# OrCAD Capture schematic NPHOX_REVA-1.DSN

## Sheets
1 001 Power: size B; title: npHOx - Power; rev: A
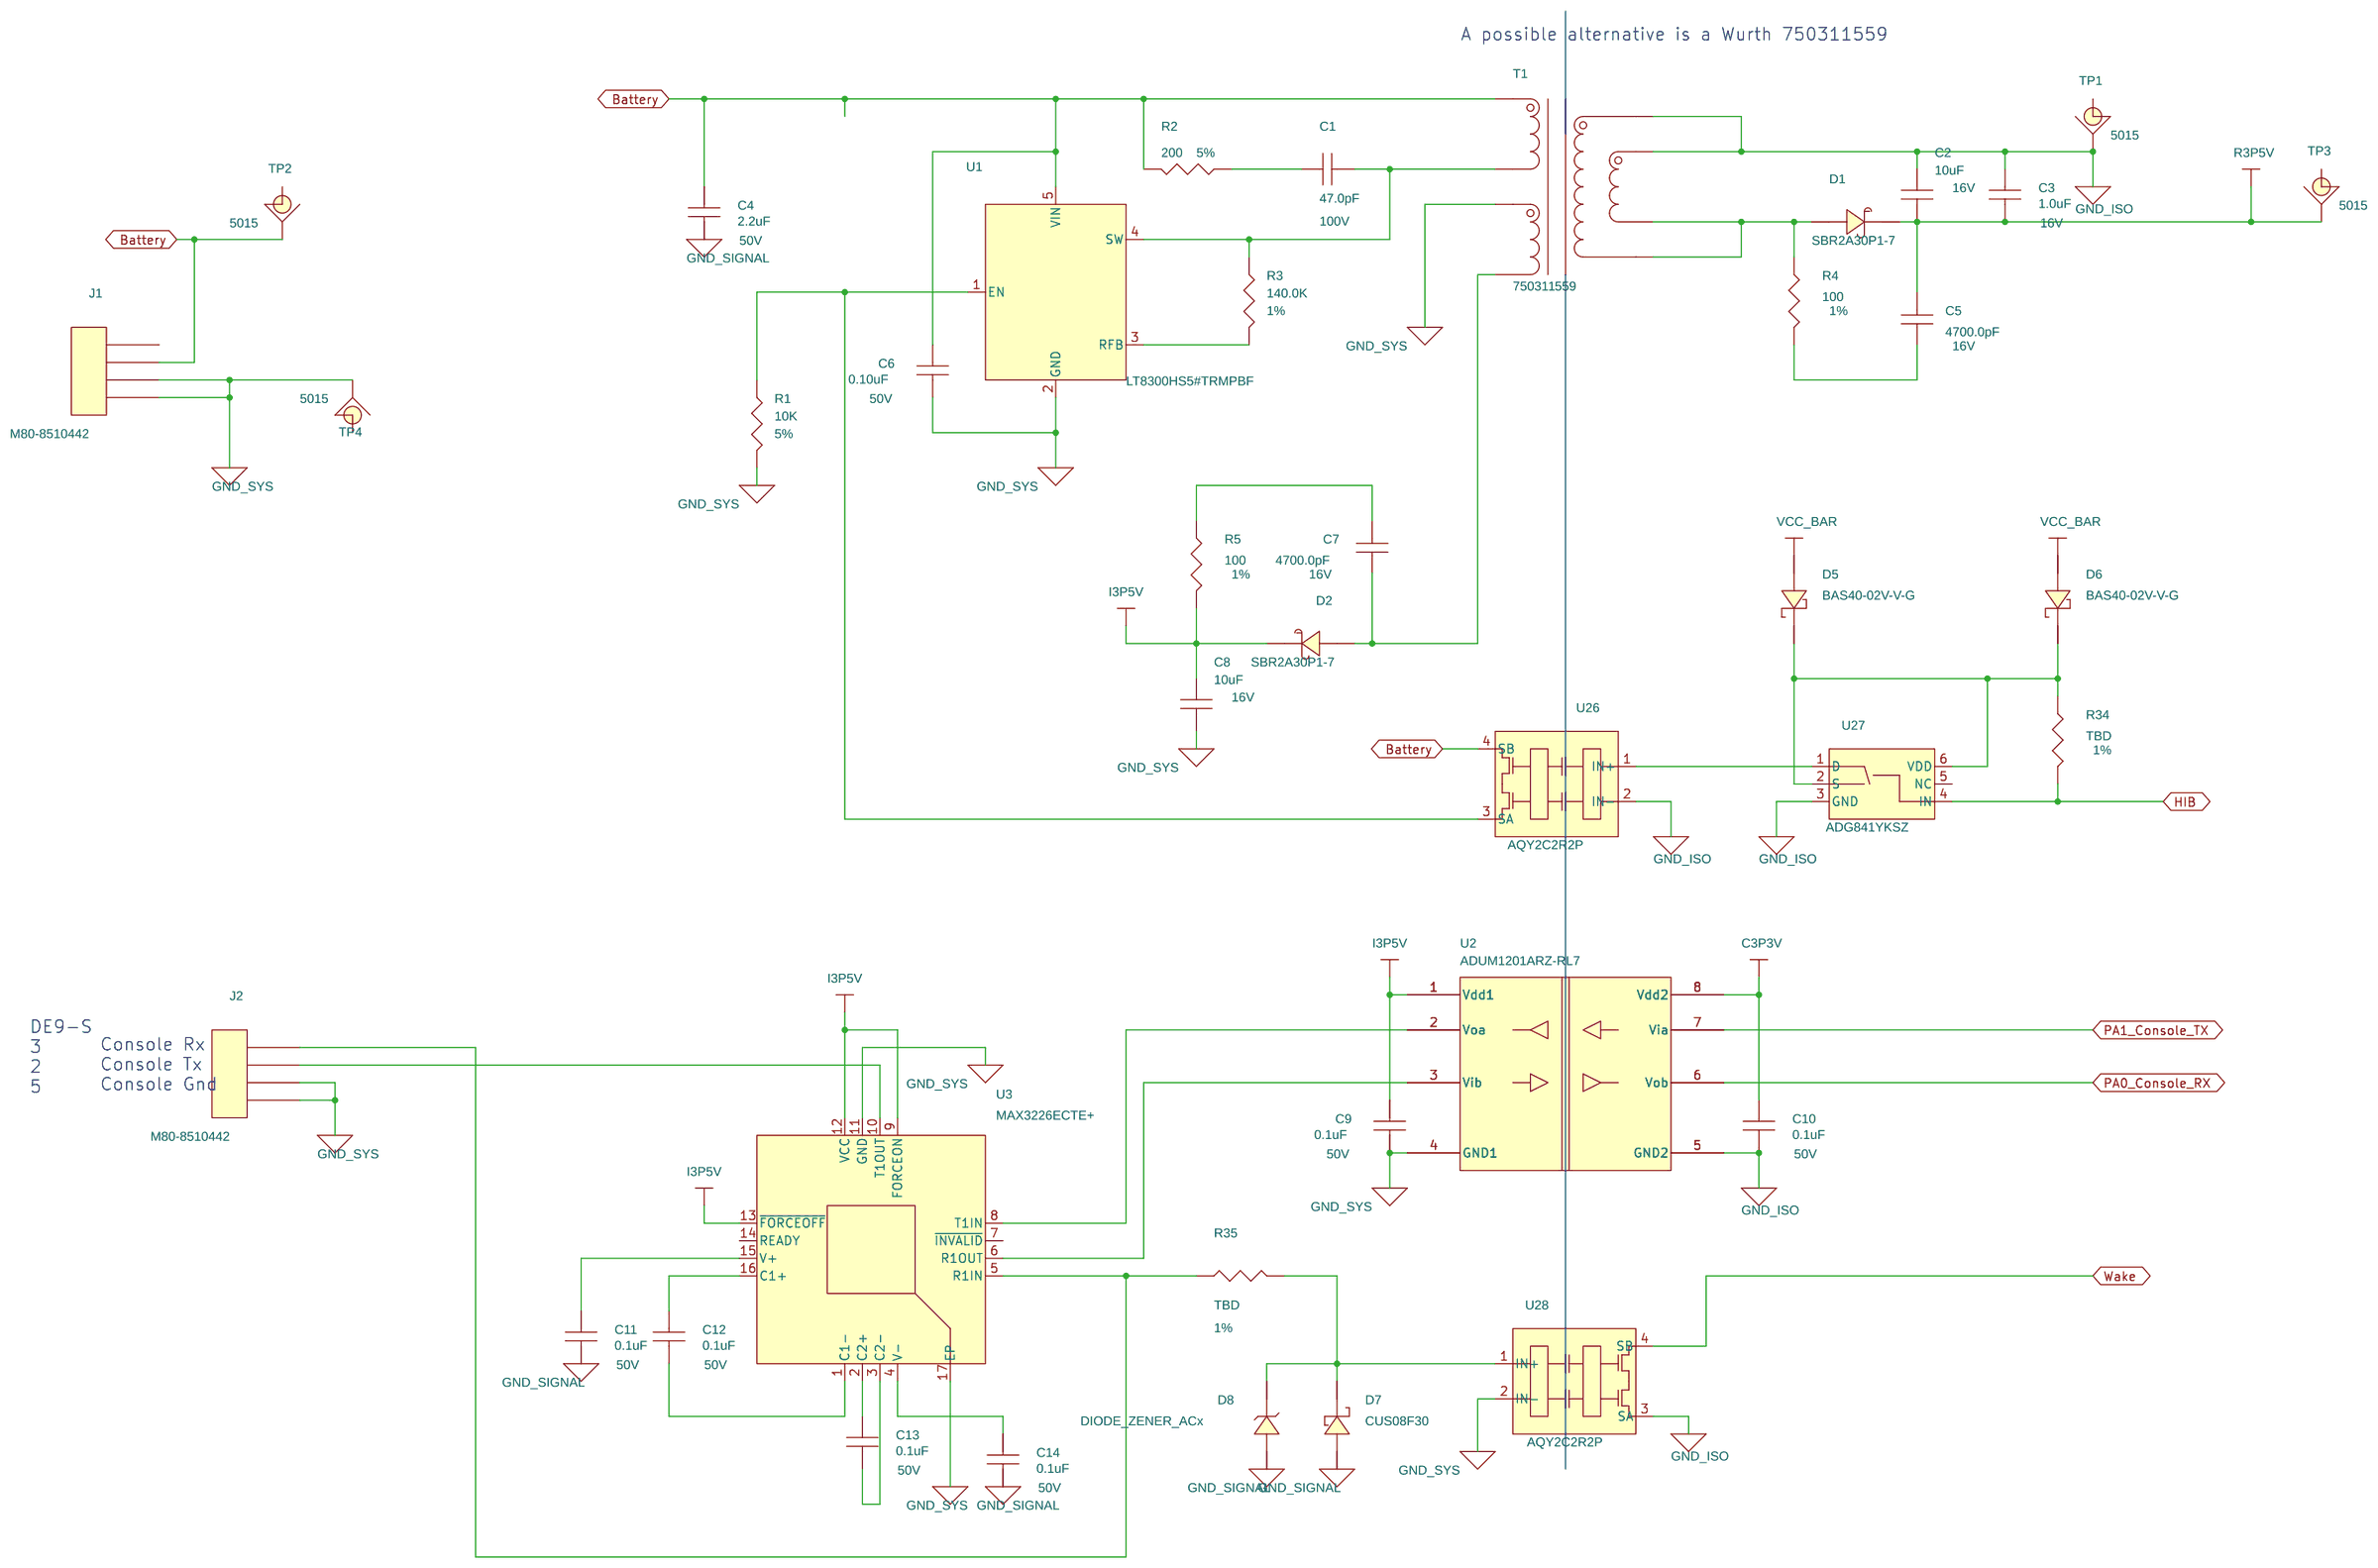
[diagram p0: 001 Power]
2 002 Voltage Regulators: size B; title: npHOx - Voltage Regulators; rev: C; note: 100221250rA
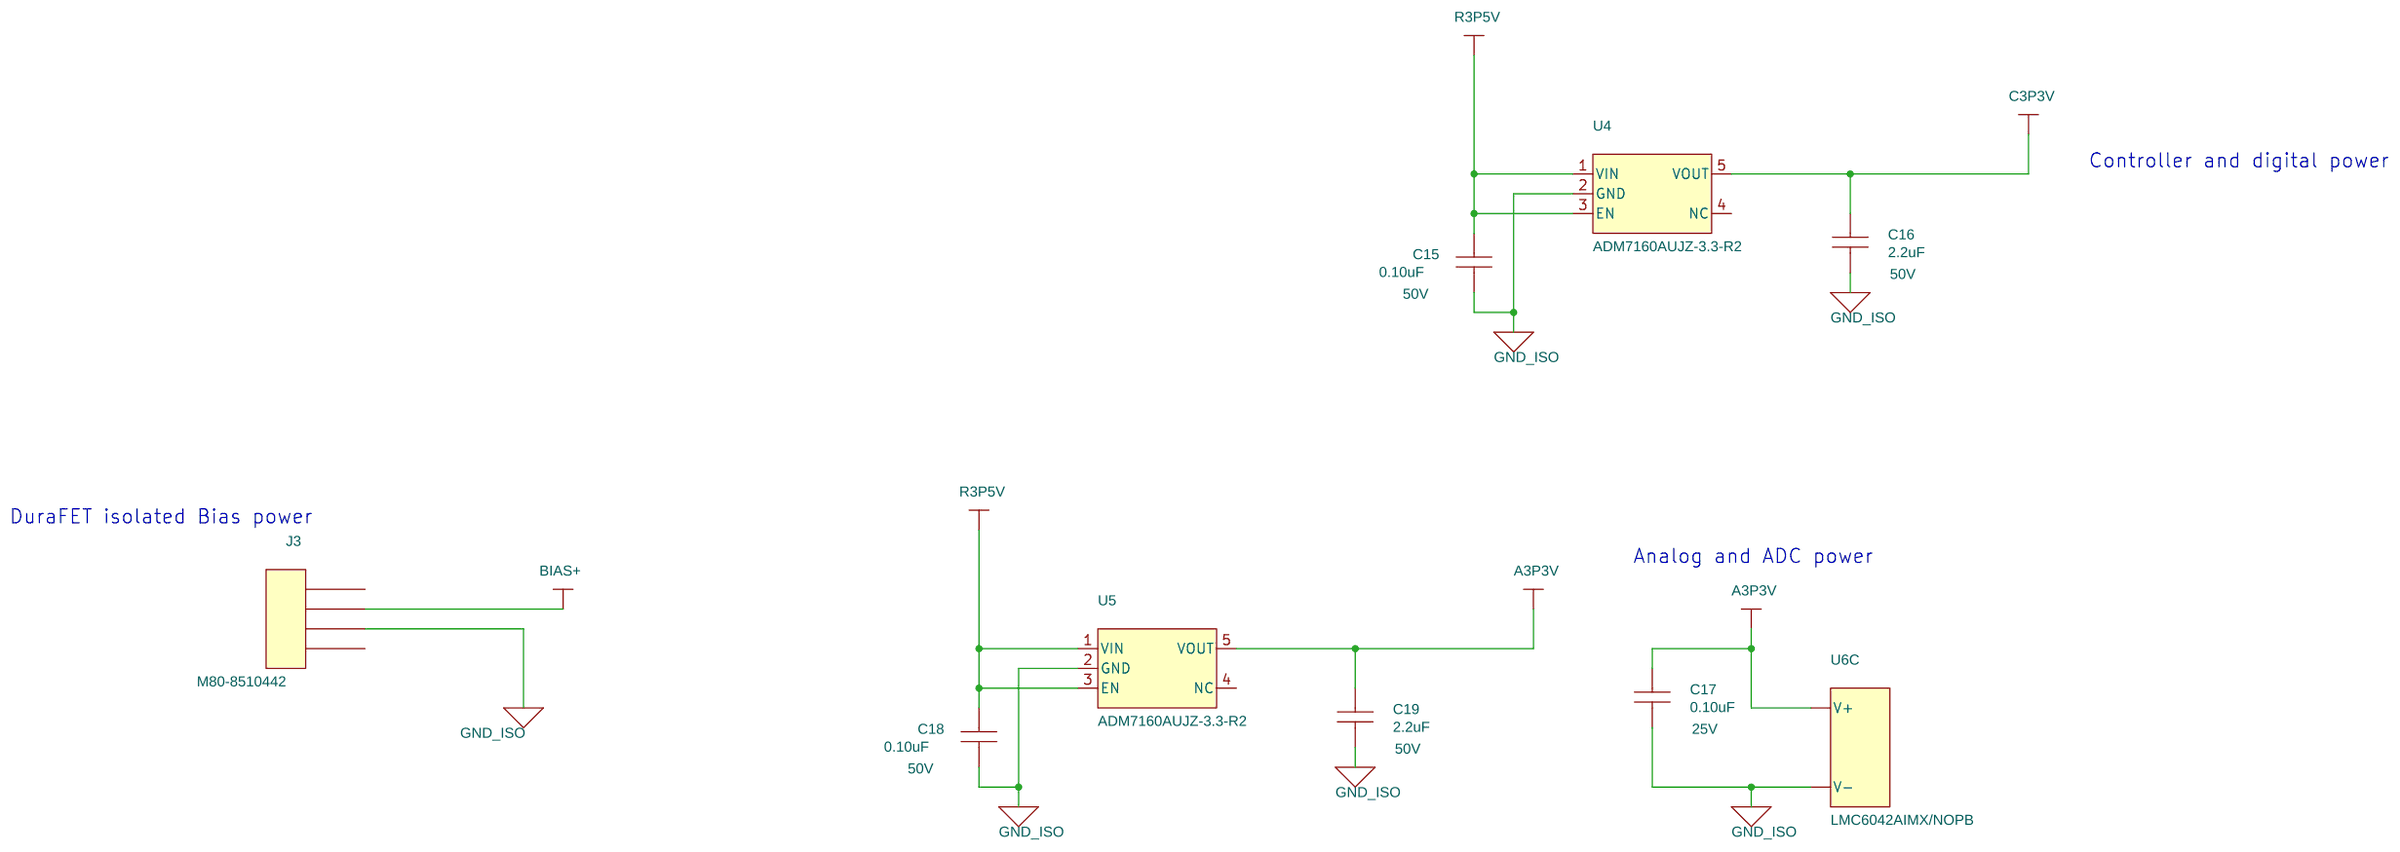
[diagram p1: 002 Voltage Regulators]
3 003 Processor: size B; title: npHOx - Processor
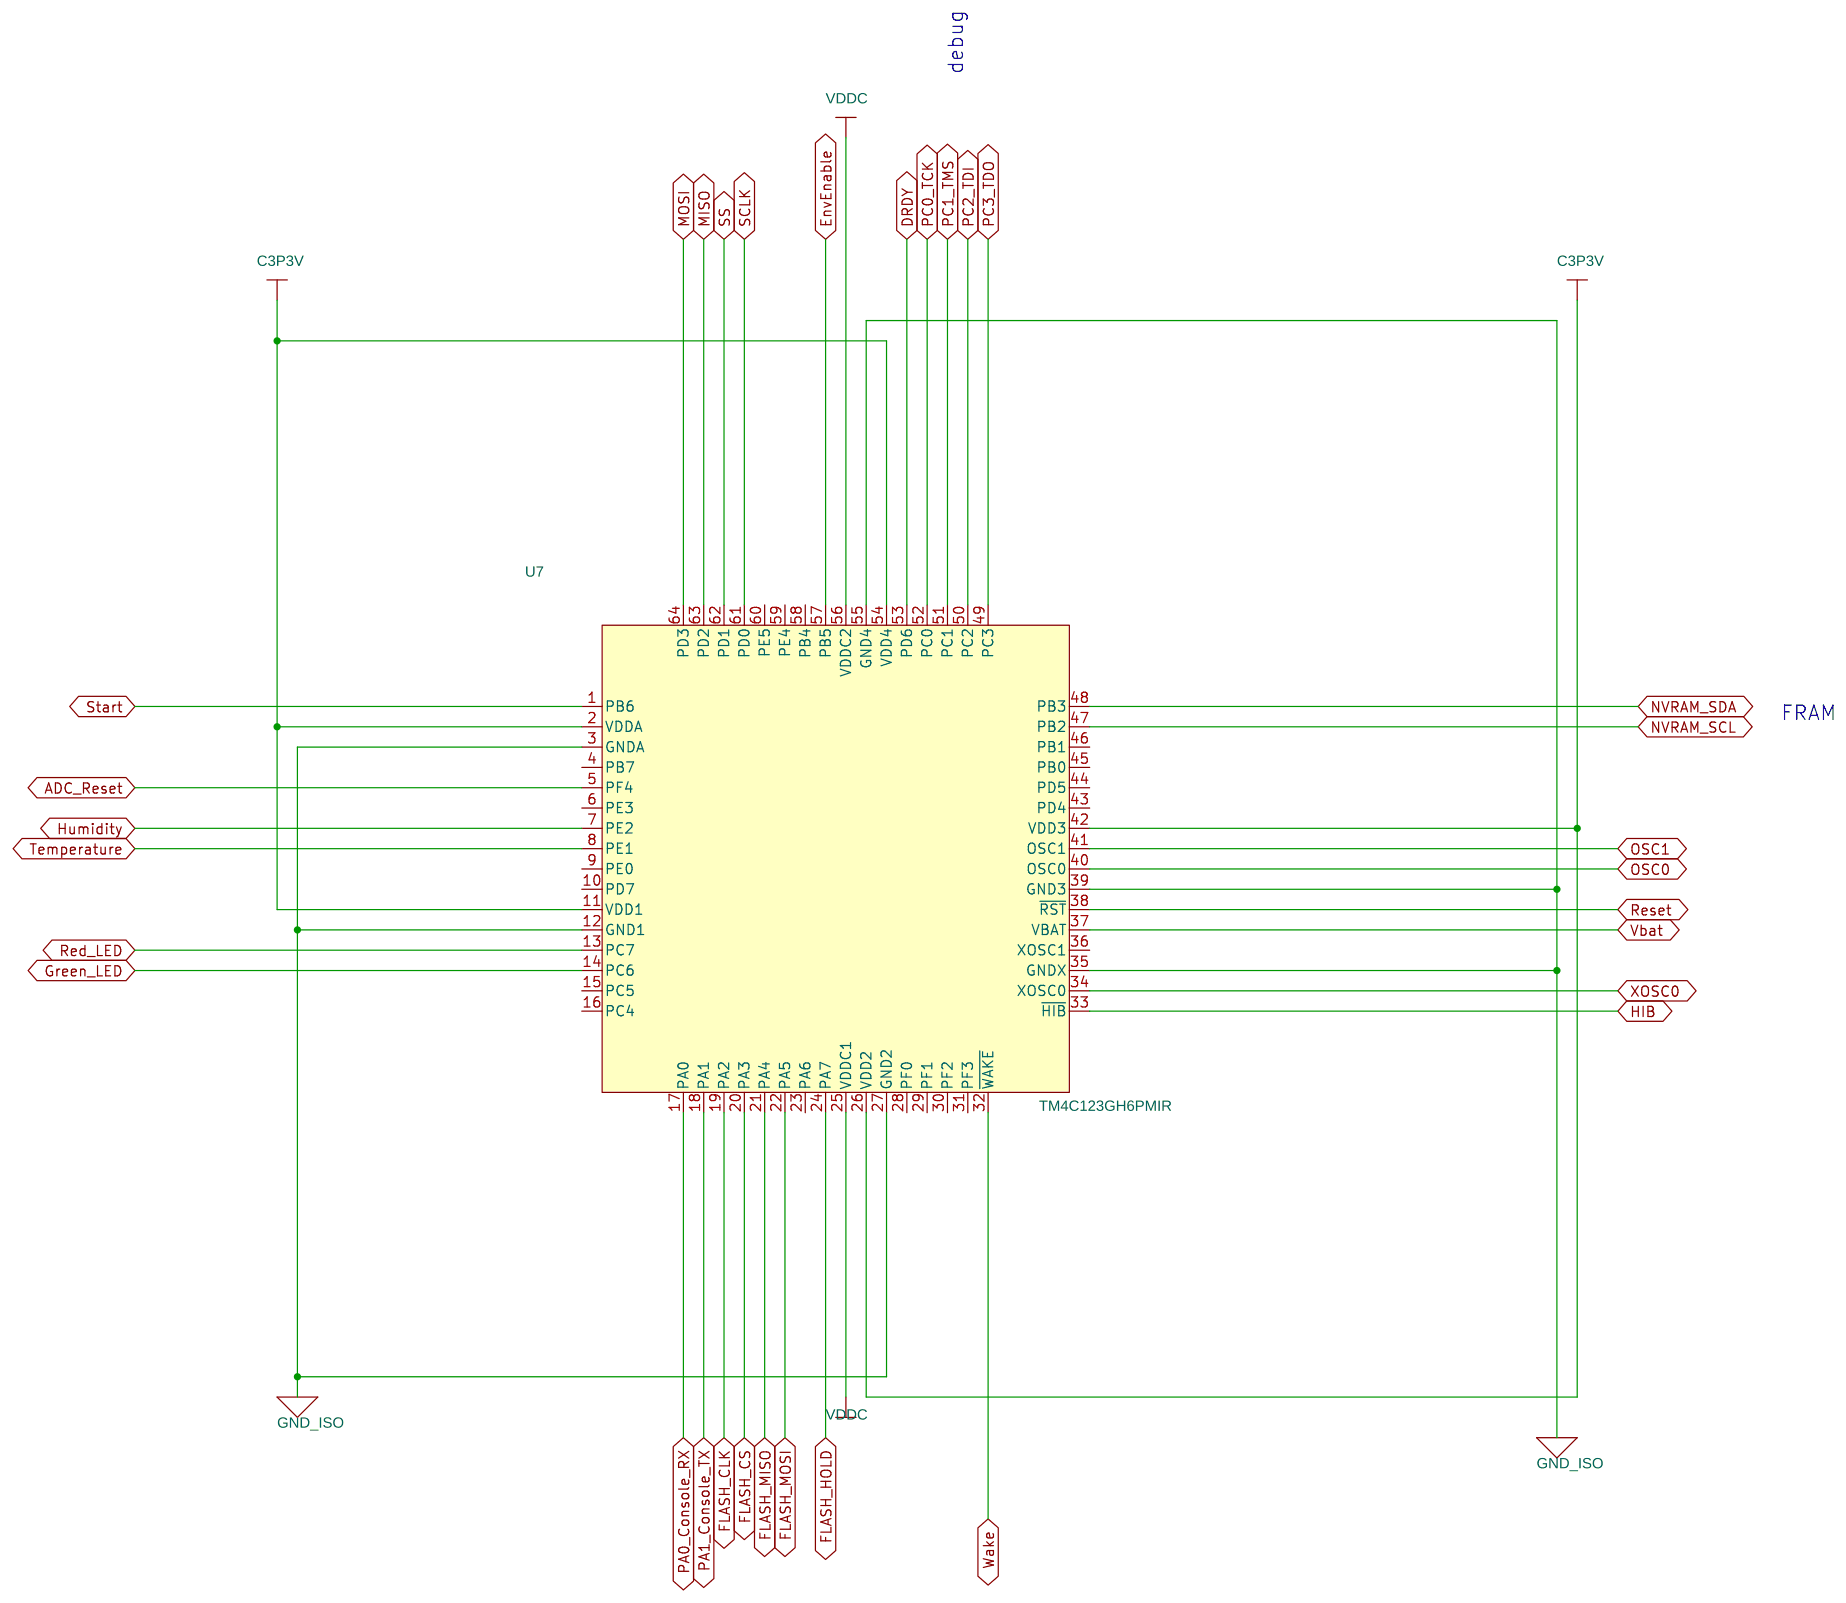
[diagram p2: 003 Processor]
4 004 Processor Bypass: size B; title: npHOx - Processor Bypass
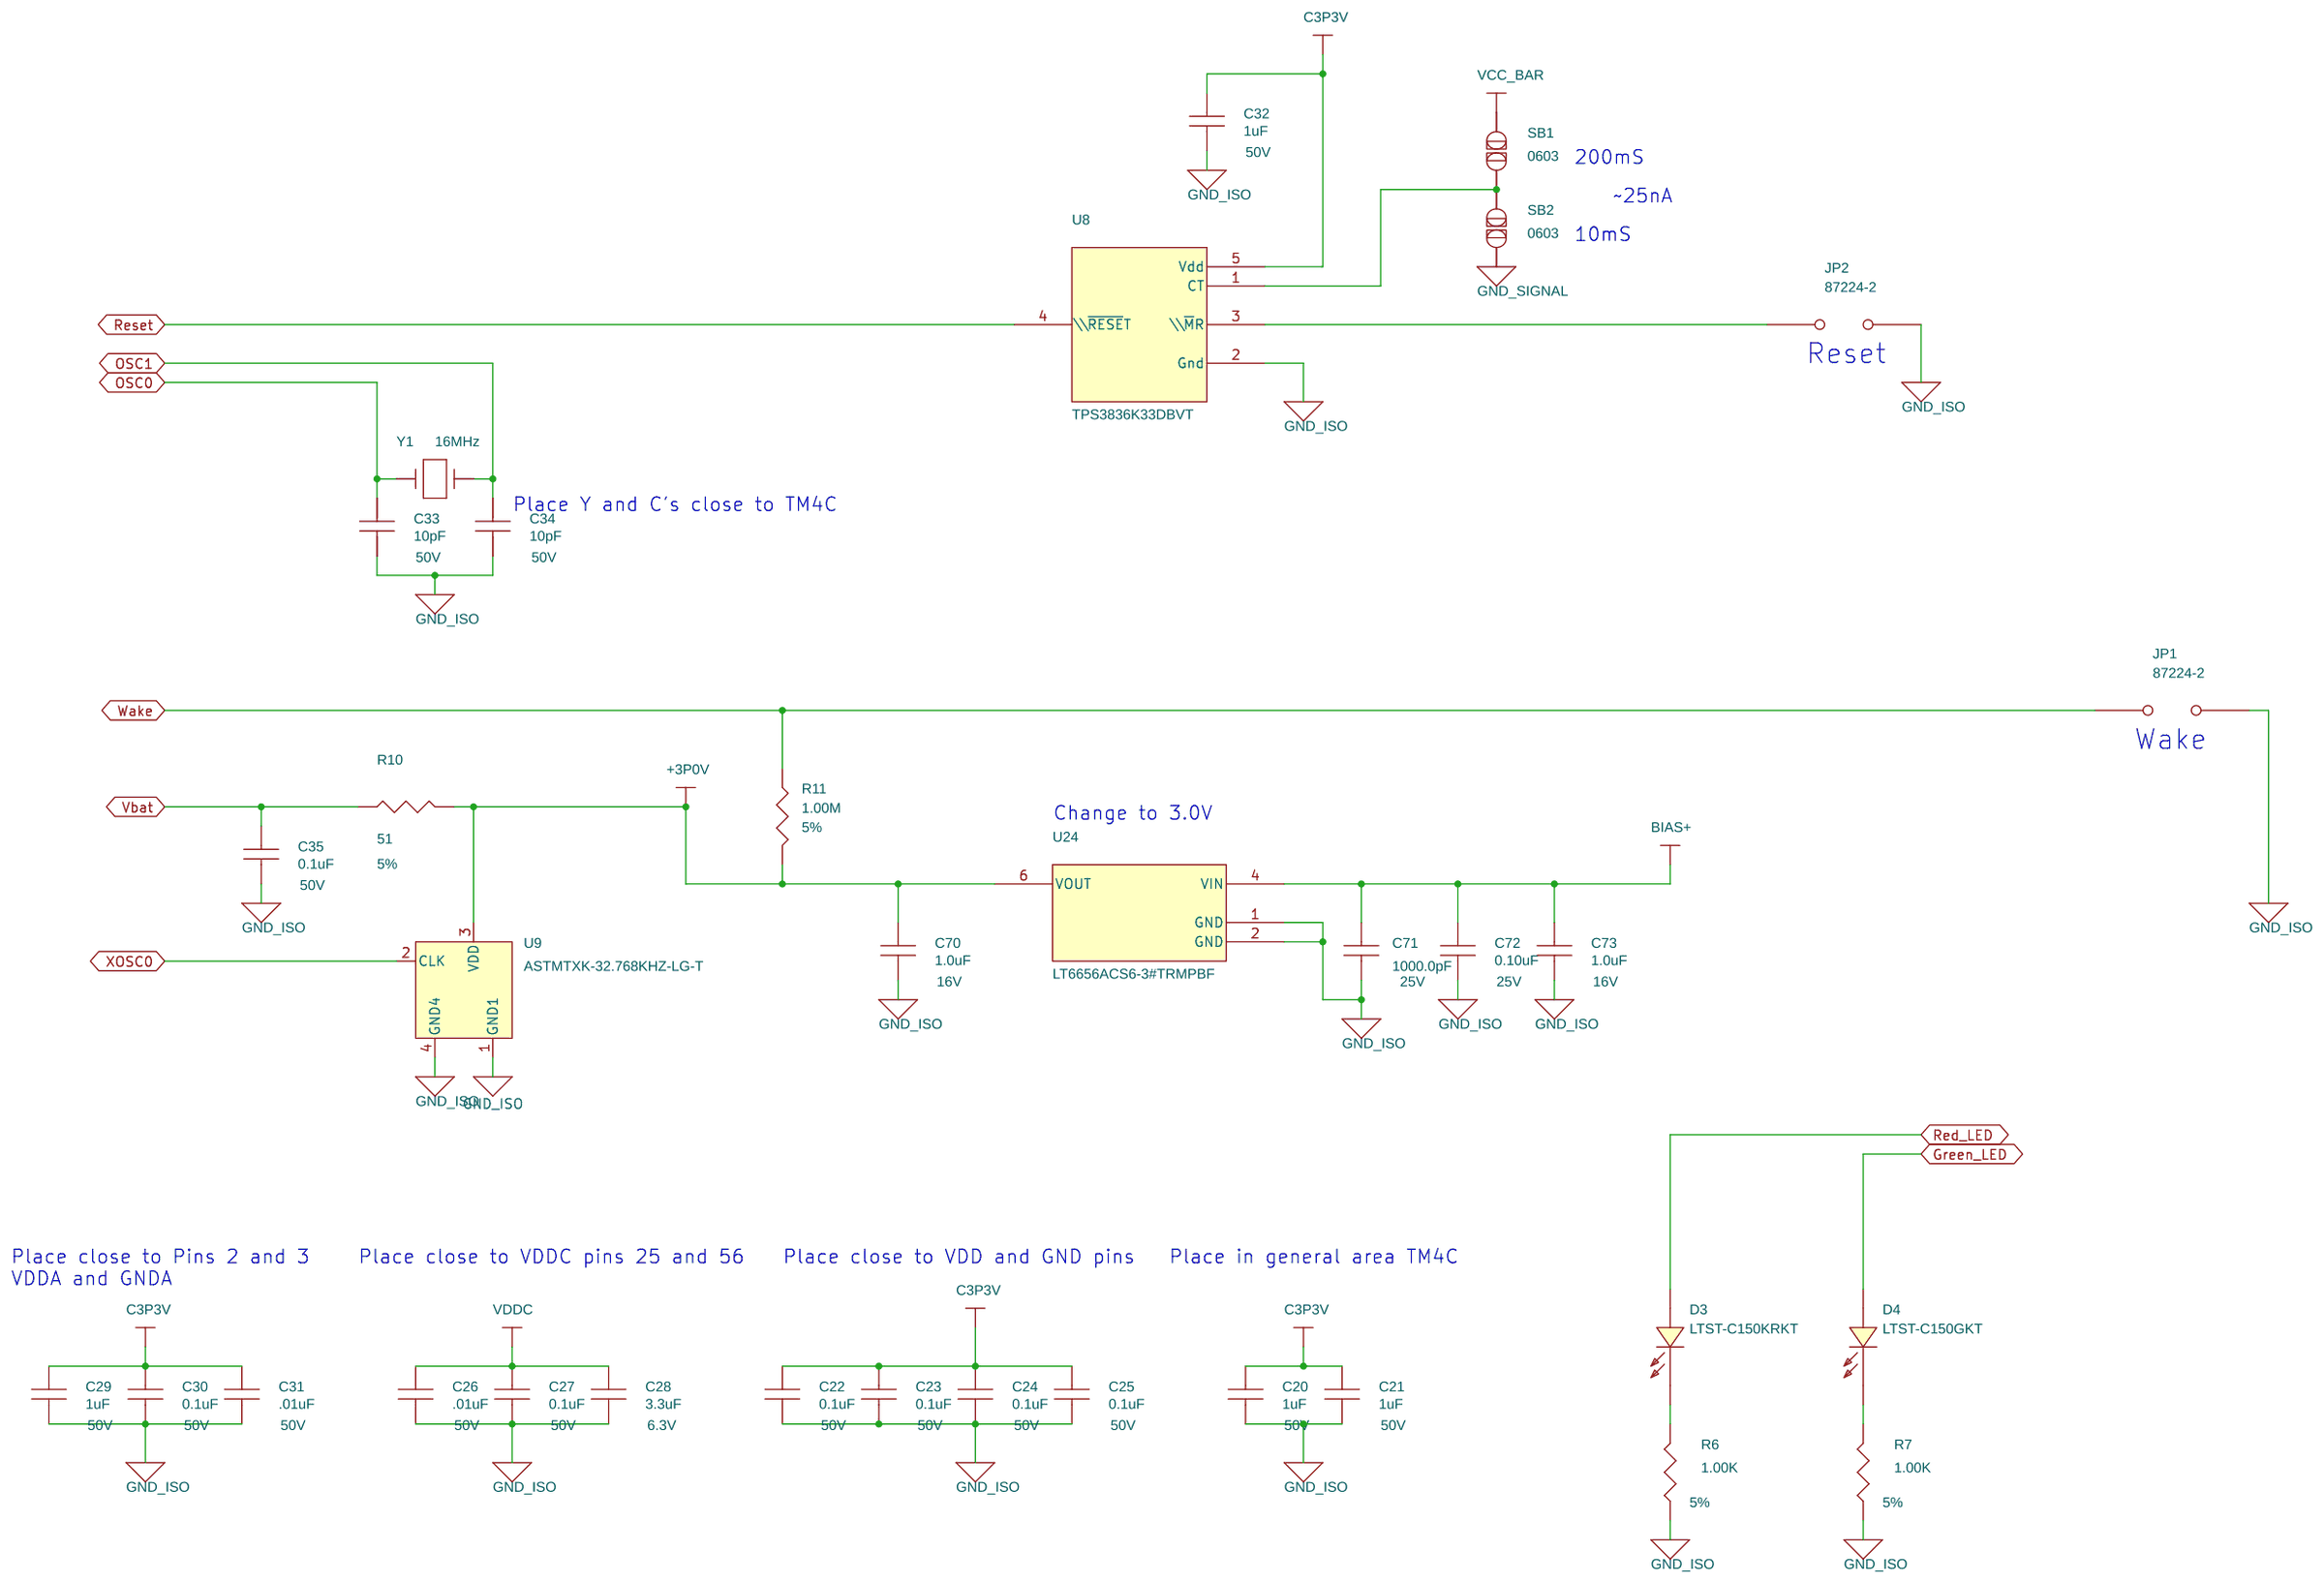
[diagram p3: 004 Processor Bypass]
5 005 Miscellaneous Interfaces: size B; title: npHOx - Miscellaneous Interfaces
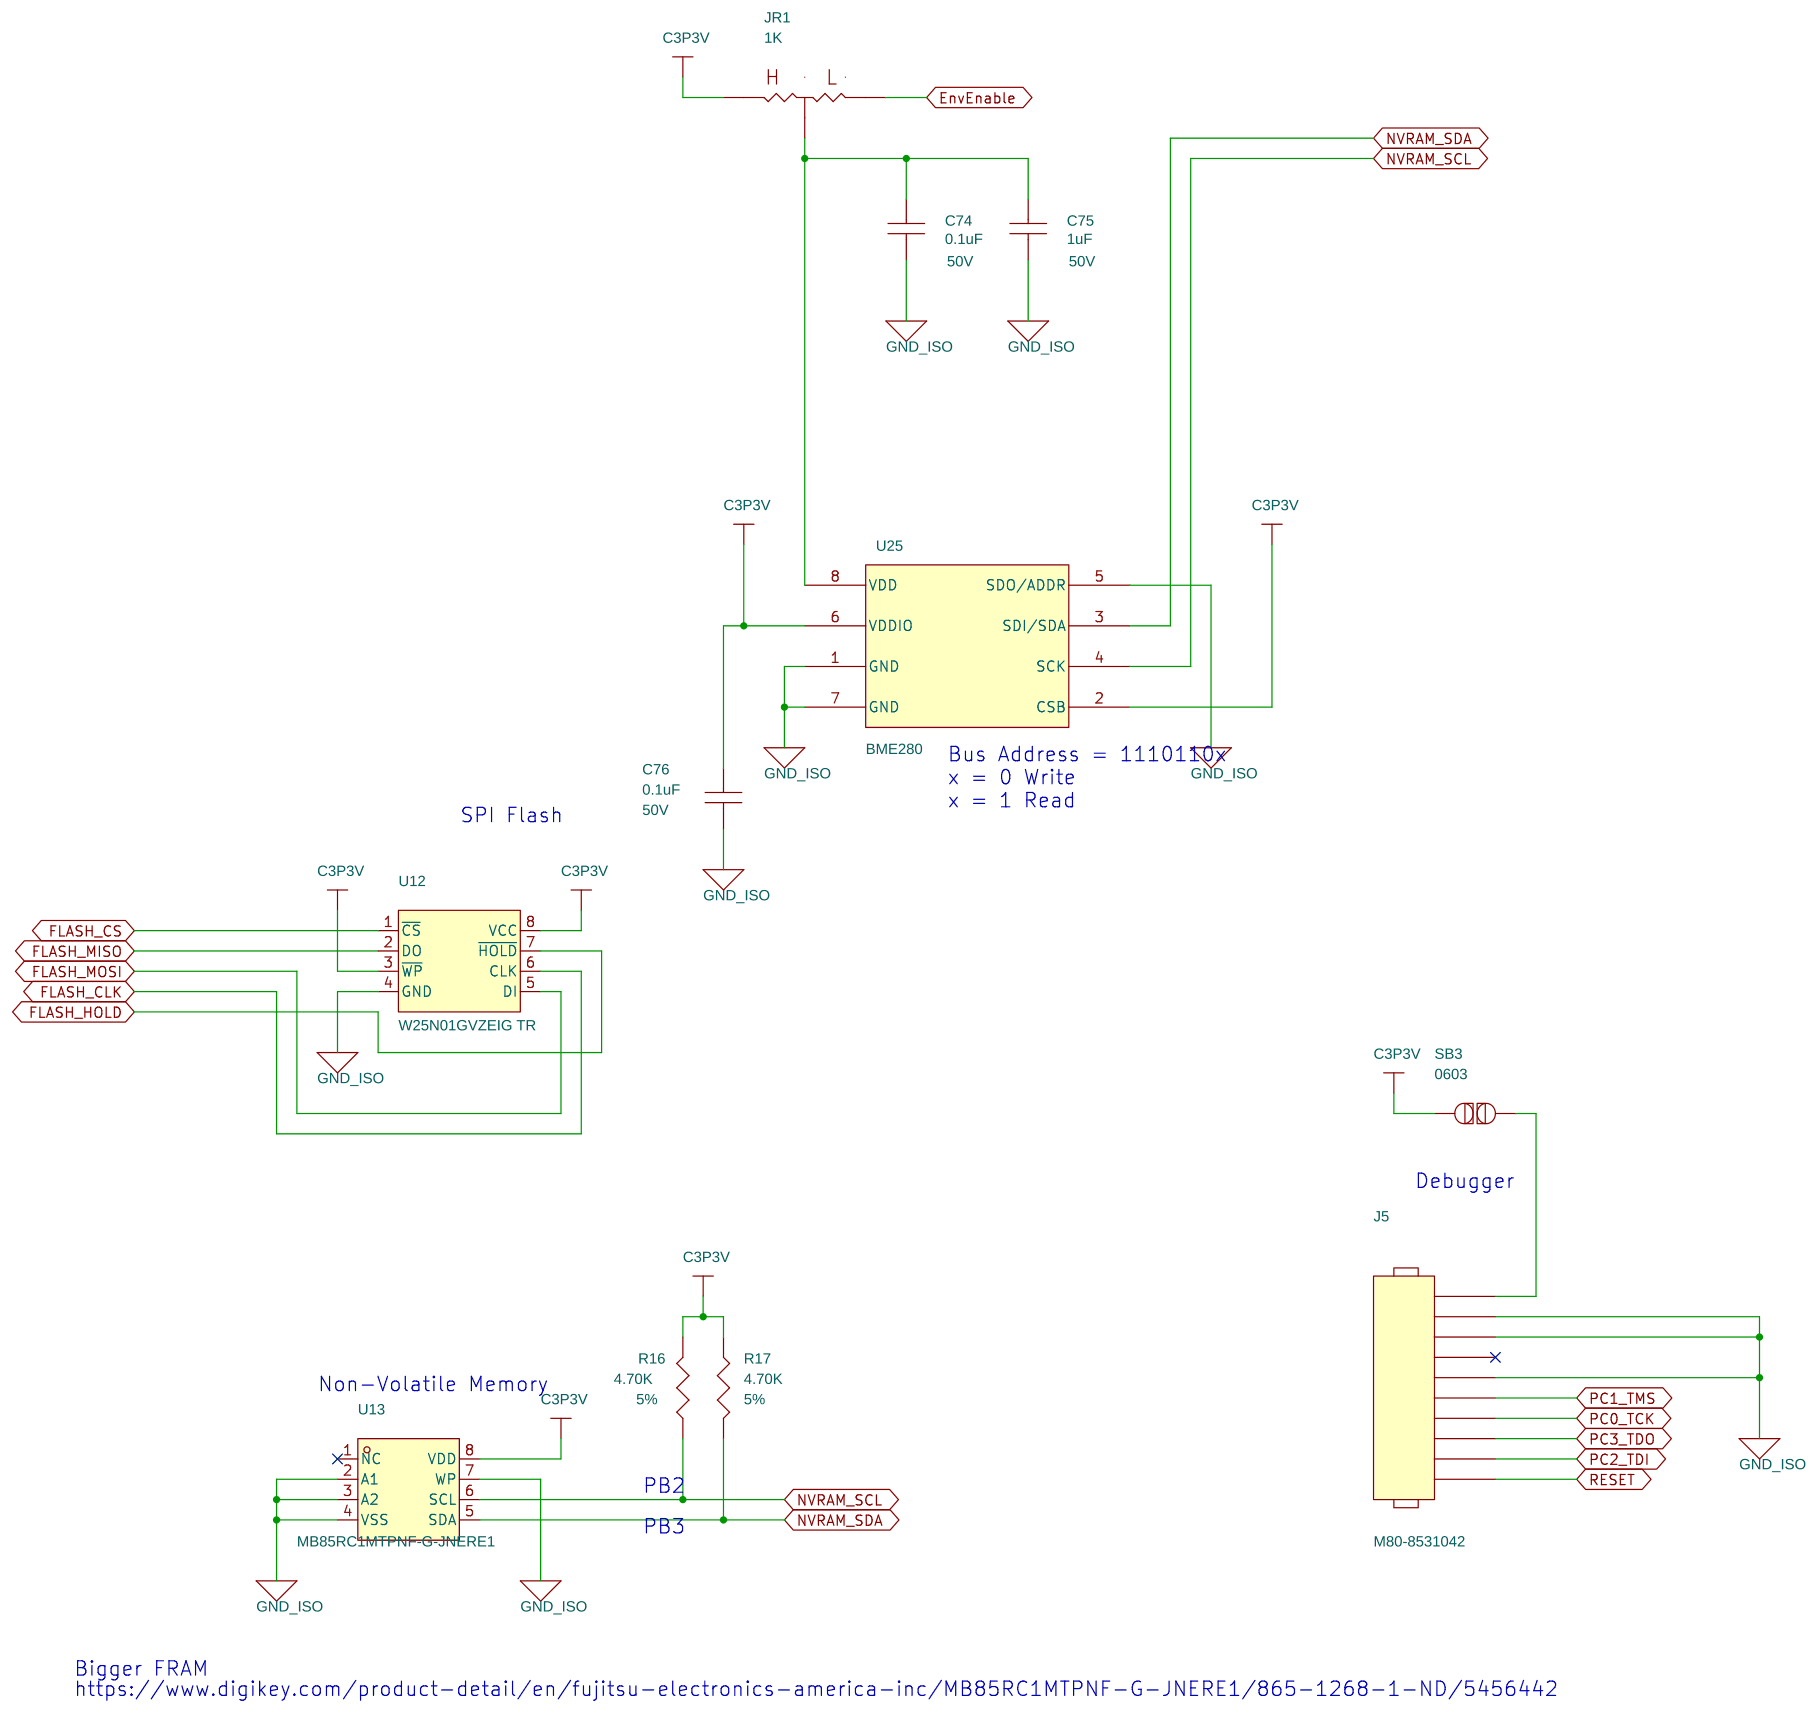
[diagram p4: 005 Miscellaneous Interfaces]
6 006 pH ADC: size B; title: npHOx - pH ADC; rev: C; note: 100221250rA
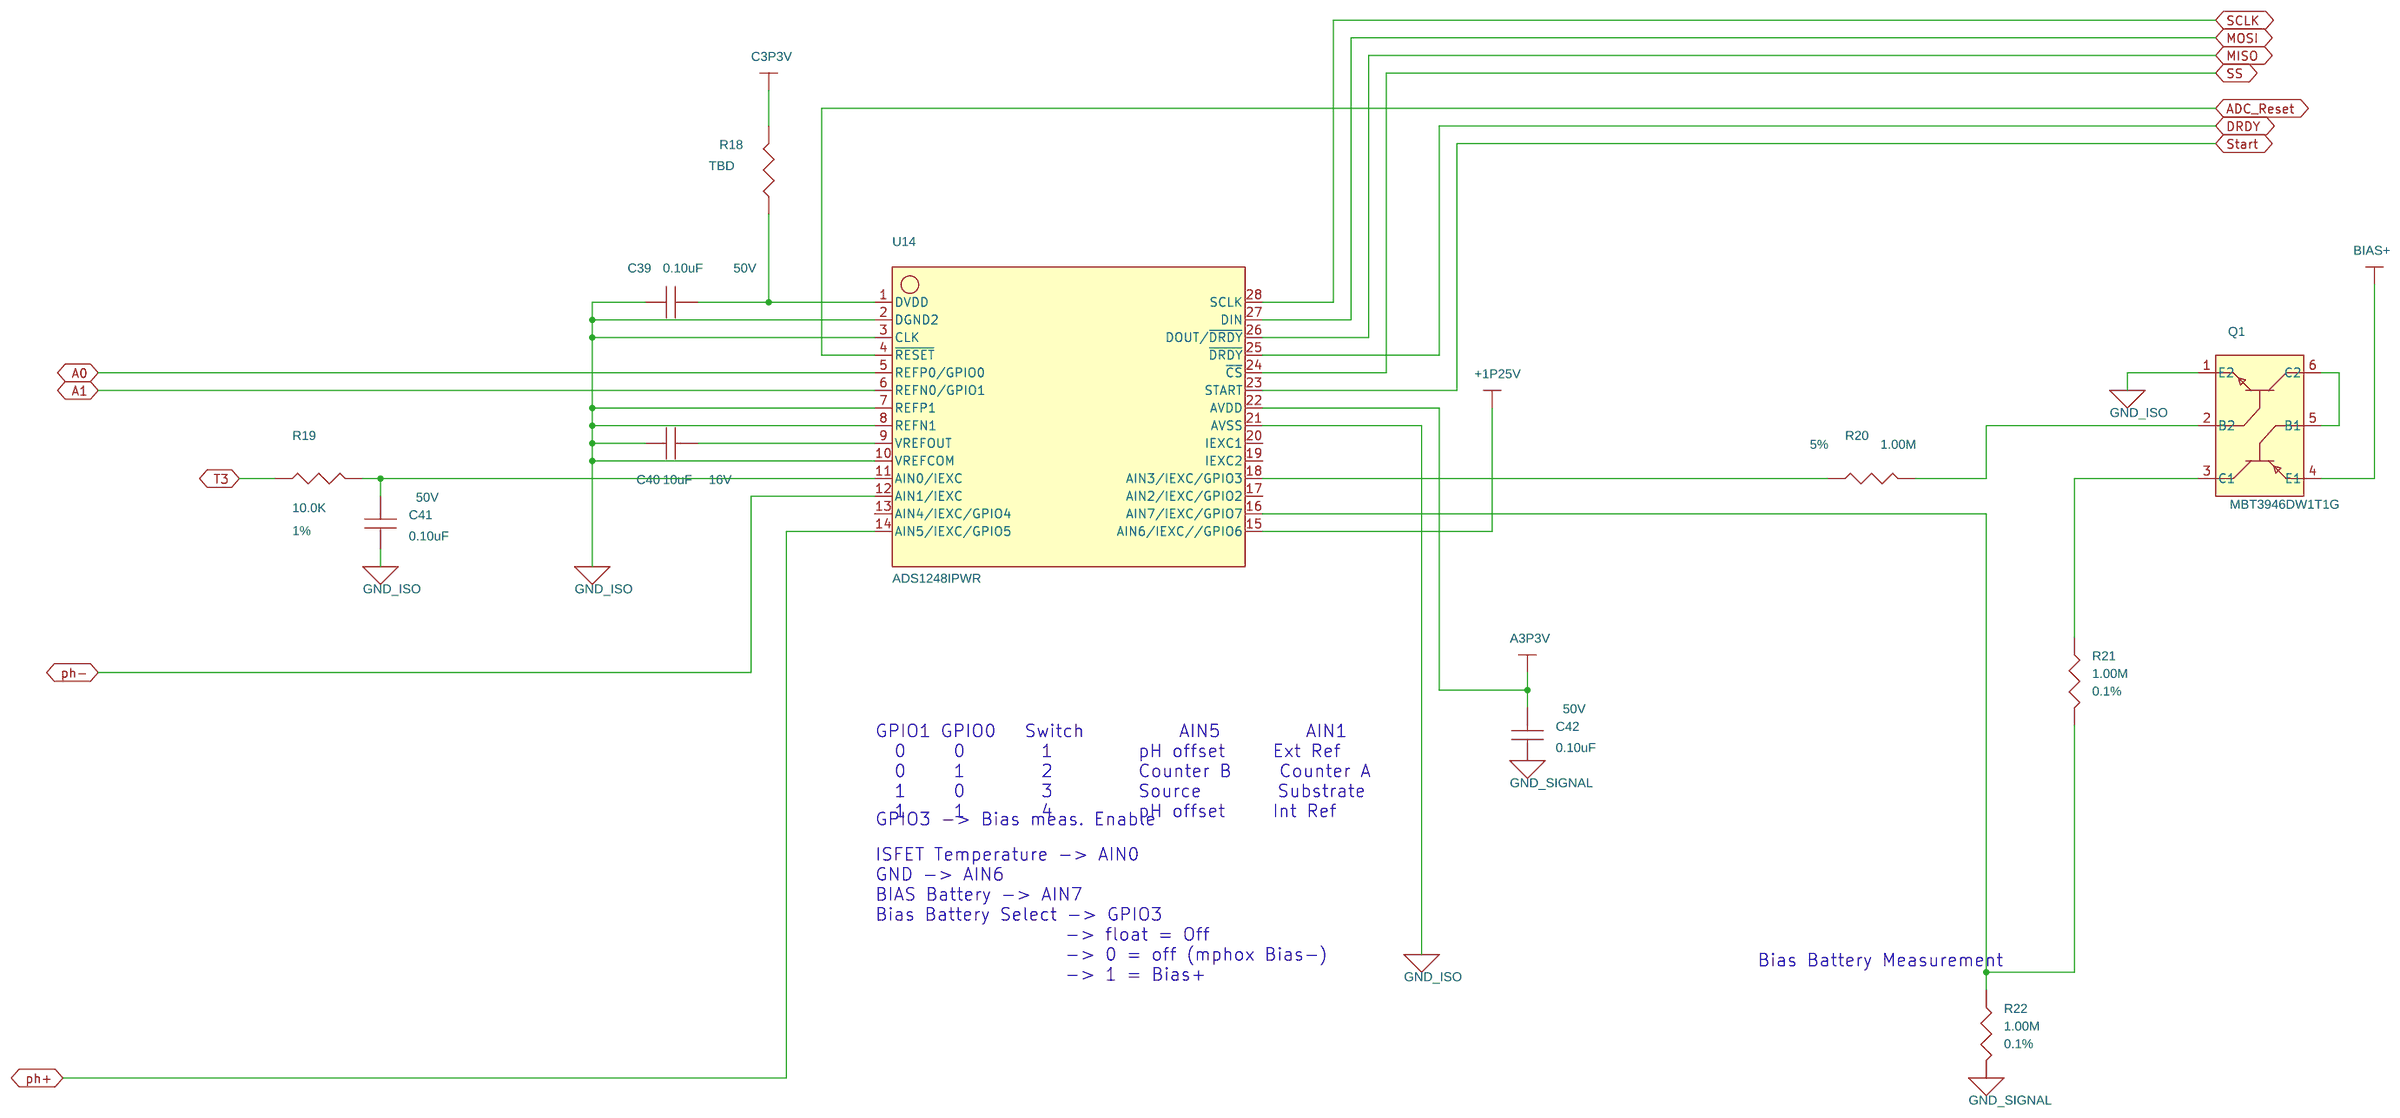
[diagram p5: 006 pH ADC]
7 007 Buffer: size B; title: npHOx - Buffer; rev: C; note: 100221250rA
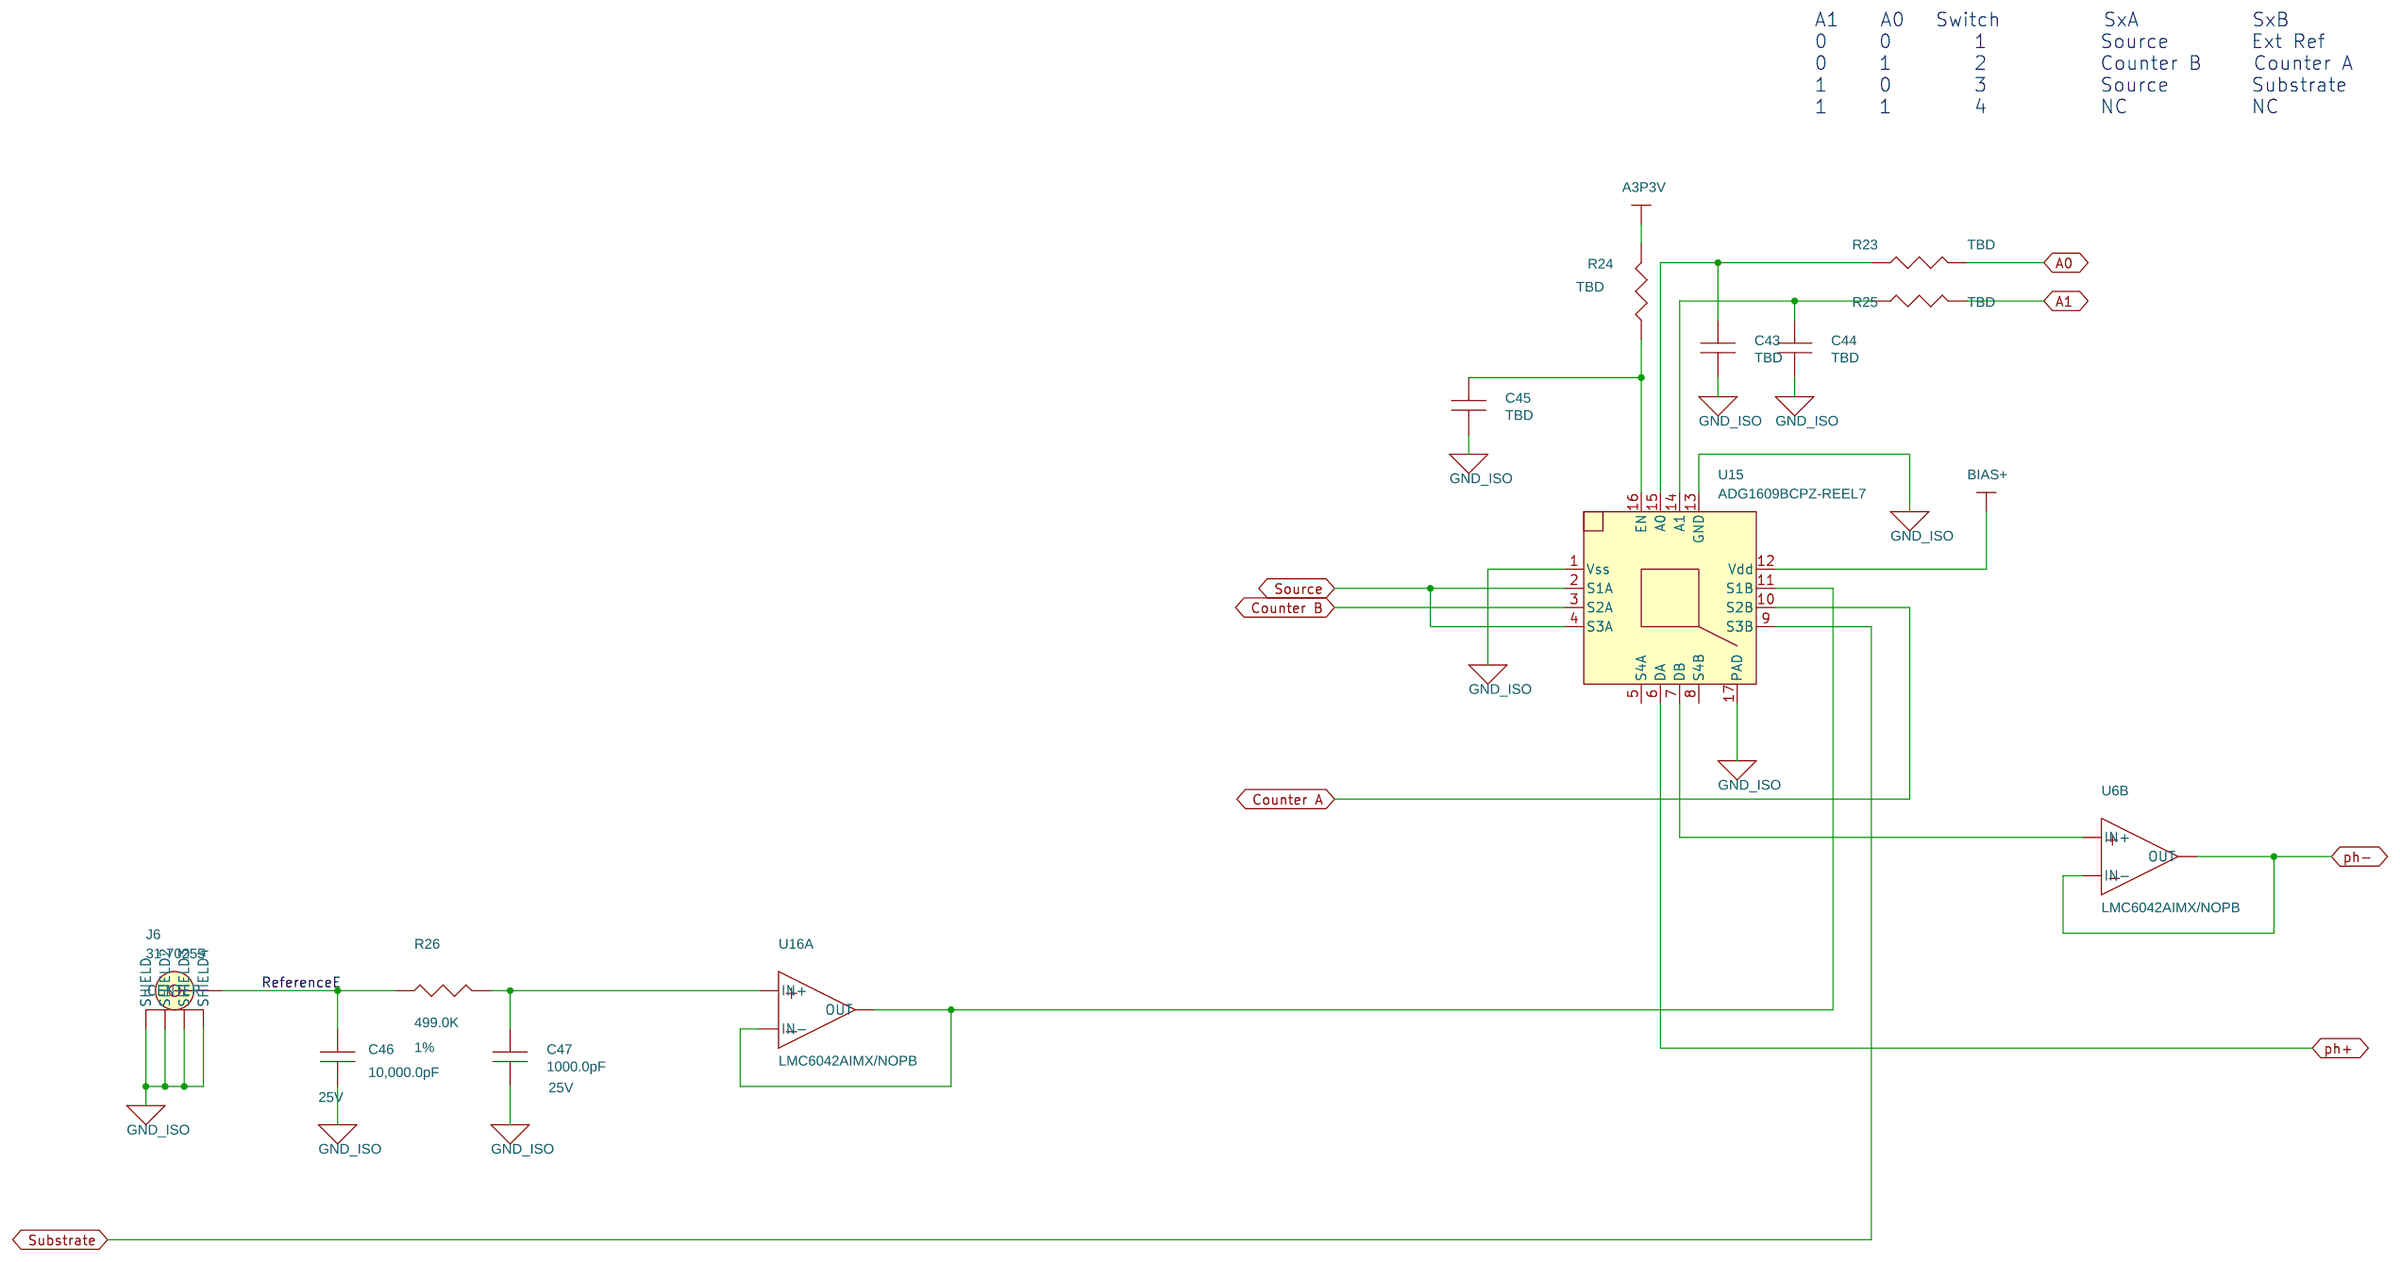
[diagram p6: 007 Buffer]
8 008 Bias: size B; title: npHOx - Bias; rev: C; note: 100221250rA
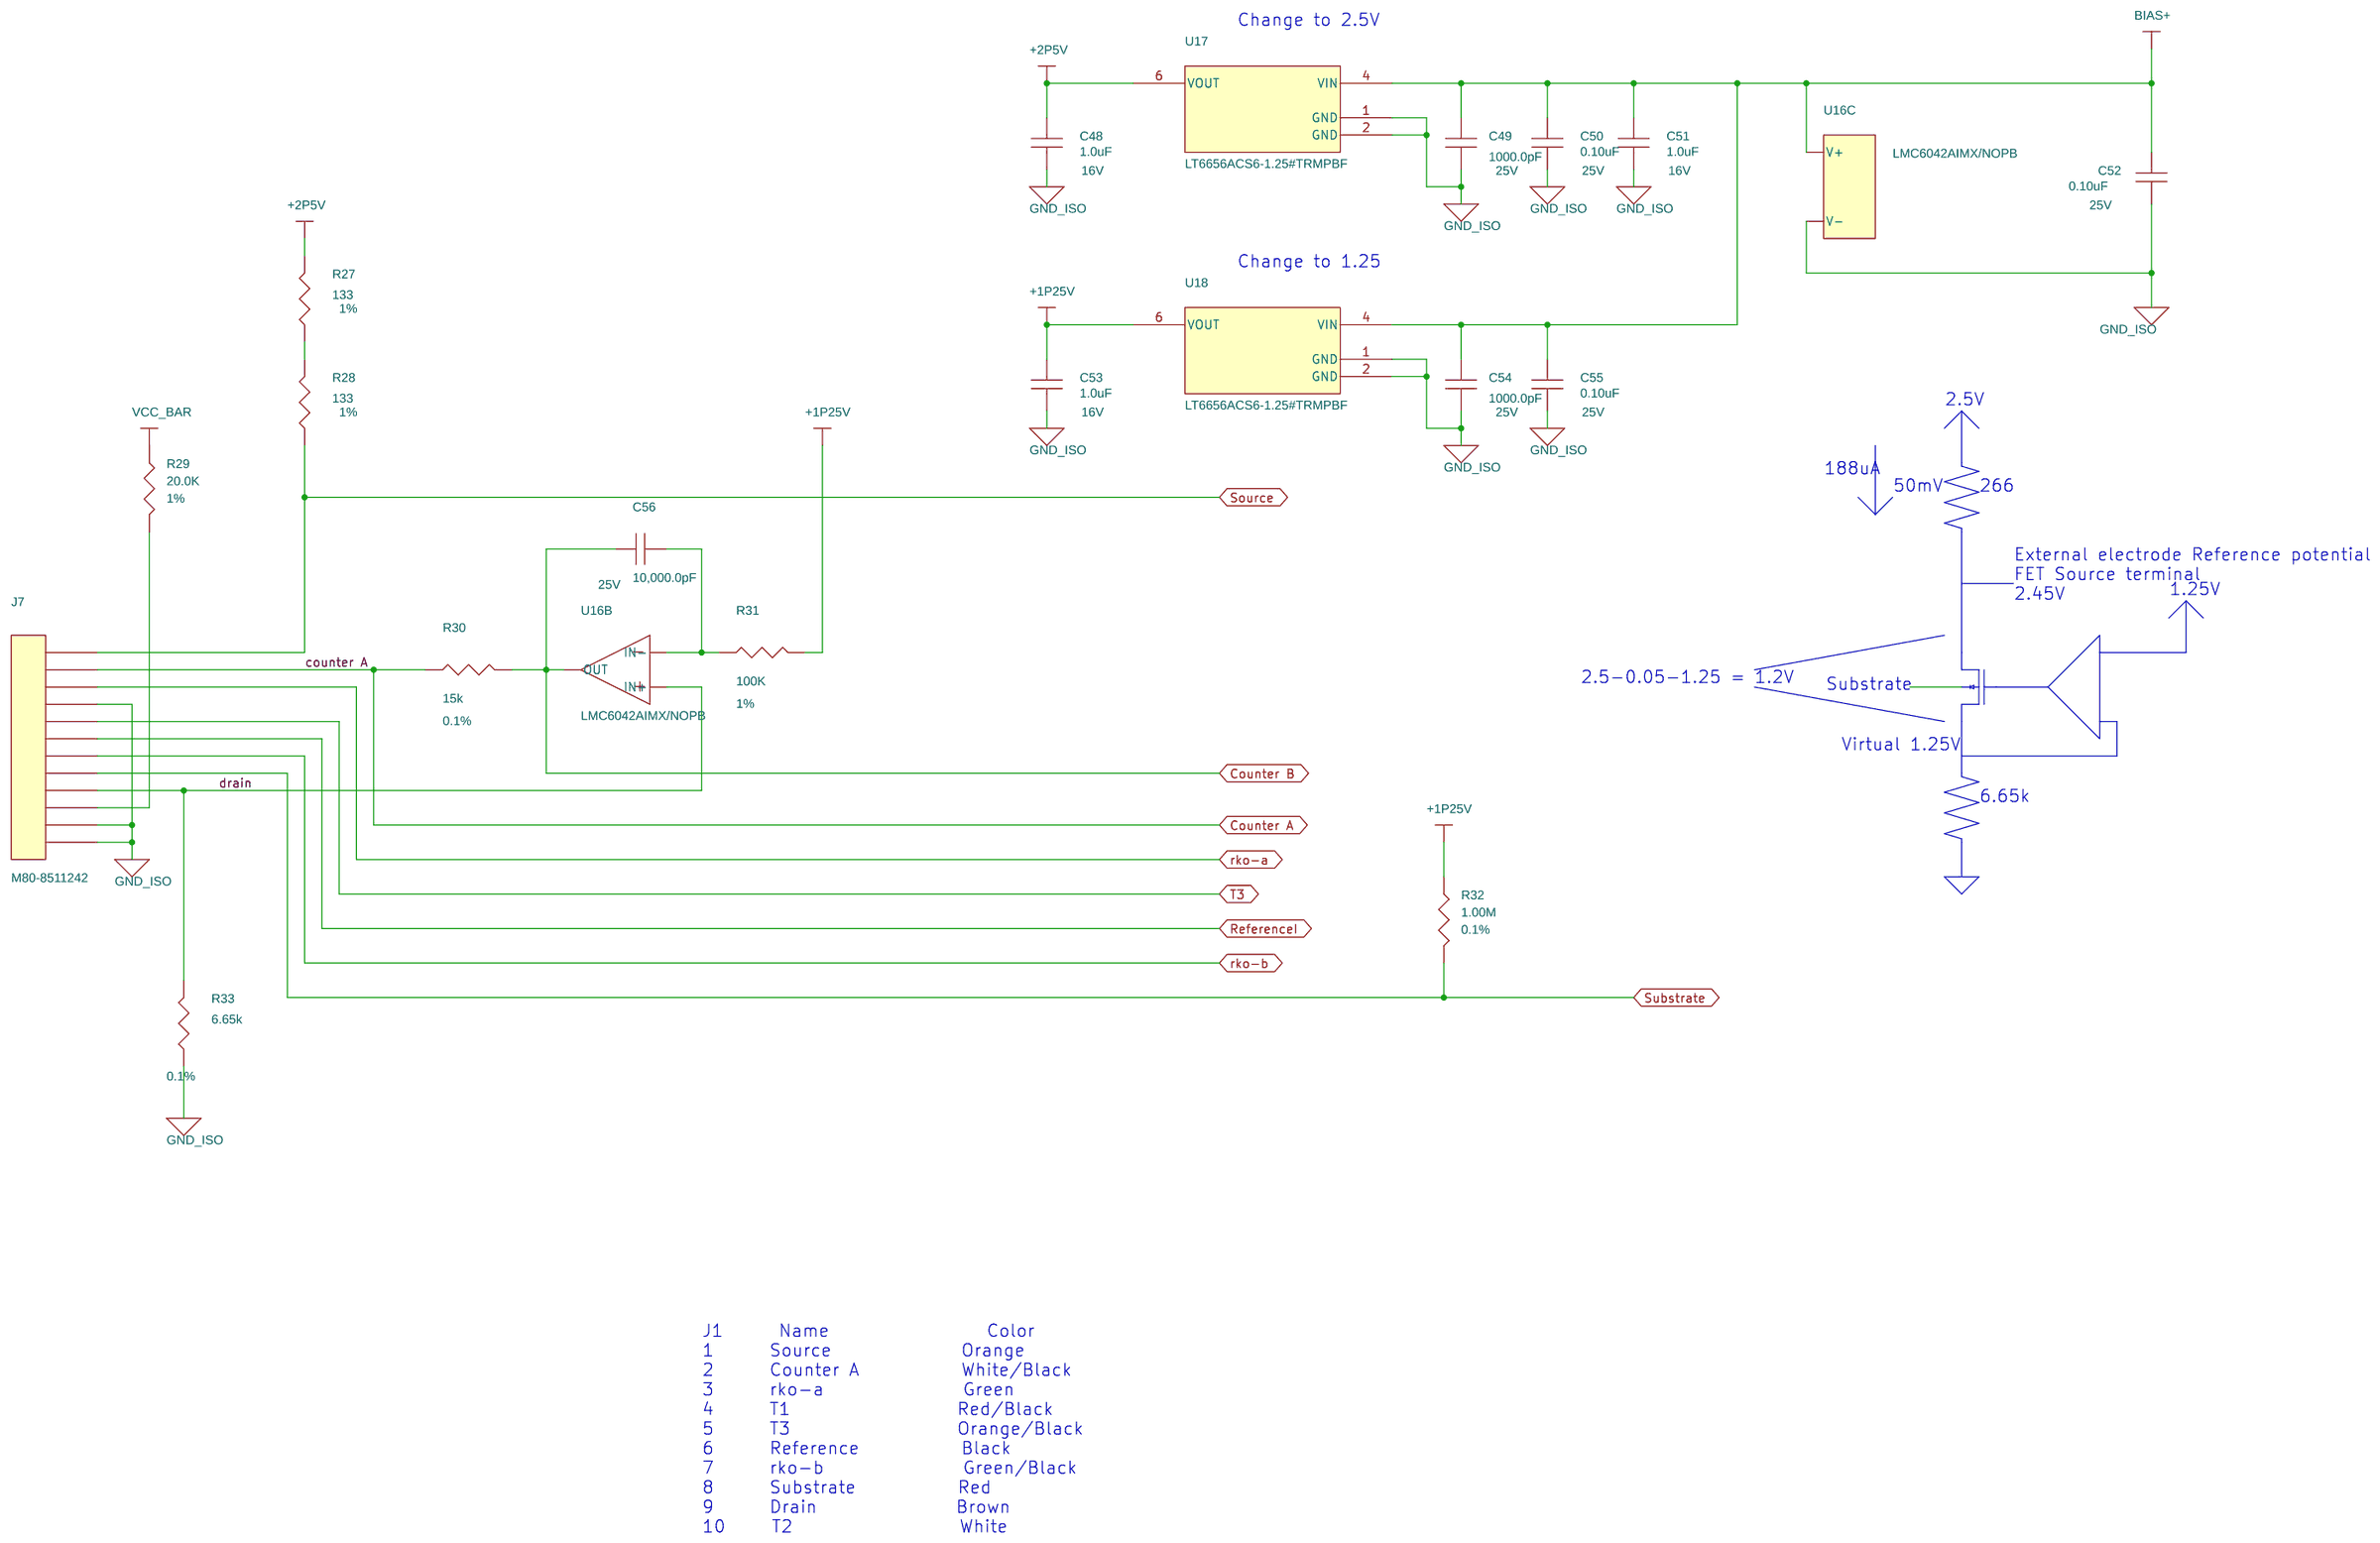
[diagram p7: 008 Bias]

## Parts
sheet 001 Power
C1  47.0pF  [CAPC1608X87N]
C2  10uF  [CAPC2012X135N]
C3  1.0uF  [CAPC1608X90N]
C4  2.2uF  [CAPC2012X145N]
C5  4700.0pF  [CAPC1608X87N]
C6  0.10uF  [AVX_LICC-0508-A_CAPC]
C7  4700.0pF  [CAPC1608X87N]
C8  10uF  [CAPC2012X135N]
C9  0.1uF  [MURATA_GCM188-0603_CAPC]
C10  0.1uF  [MURATA_GCM188-0603_CAPC]
C11  0.1uF  [MURATA_GCM188-0603_CAPC]
C12  0.1uF  [MURATA_GCM188-0603_CAPC]
C13  0.1uF  [MURATA_GCM188-0603_CAPC]
C14  0.1uF  [MURATA_GCM188-0603_CAPC]
D1  SBR2A30P1-7  [SODFL3717X100N]
D2  SBR2A30P1-7  [SODFL3717X100N]
D5  BAS40-02V-V-G
D6  BAS40-02V-V-G
D7  CUS08F30
D8  DIODE_ZENER_ACx
J1  M80-8510442  [HARWIN_M80-851_4PIN]
J2  M80-8510442  [HARWIN_M80-851_4PIN]
R1  10K  [RESC1608X50N]
R2  200  [RESC1608X50N]
R3  140.0K  [RESC1608X50N]
R4  100  [VISHAY_CRCW-0603_RESC]
R5  100  [VISHAY_CRCW-0603_RESC]
R34  TBD  [VISHAY_CRCW-0603_RESC]
R35  TBD  [VISHAY_CRCW-0603_RESC]
T1  750311559  [WURTH_750311559]
TP1  5015  [TP_5015]
TP2  5015  [TP_5015]
TP3  5015  [TP_5015]
TP4  5015  [TP_5015]
U1  LT8300HS5#TRMPBF  [SOT95P280X100-5L20N]
U2  ADUM1201ARZ-RL7  [SOIC127P600X175-8L87N]
U3  MAX3226ECTE+  [MAXIM_TQFN-EP_16PIN]
U26  AQY2C2R2P
U27  ADG841YKSZ
U28  AQY2C2R2P
sheet 002 Voltage Regulators
C15  0.10uF  [AVX_LICC-0508-A_CAPC]
C16  2.2uF  [CAPC2012X145N]
C17  0.10uF  [CAPC1608X87N]
C18  0.10uF  [AVX_LICC-0508-A_CAPC]
C19  2.2uF  [CAPC2012X145N]
J3  M80-8510442  [HARWIN_M80-851_4PIN]
U4  ADM7160AUJZ-3.3-R2  [SOT23-5P95_280X100L45X40N]
U5  ADM7160AUJZ-3.3-R2  [SOT23-5P95_280X100L45X40N]
U6  LMC6042AIMX/NOPB  [SOIC127P600X175-8L87N]  (sections B,C)
sheet 003 Processor
U7  TM4C123GH6PMIR  [TI_LQFP_64PIN]
sheet 004 Processor Bypass
C20  1uF  [CAPC160X80X90L30N]
C21  1uF  [CAPC160X80X90L30N]
C22  0.1uF  [MURATA_GCM188-0603_CAPC]
C23  0.1uF  [MURATA_GCM188-0603_CAPC]
C24  0.1uF  [MURATA_GCM188-0603_CAPC]
C25  0.1uF  [MURATA_GCM188-0603_CAPC]
C26  .01uF  [CAPC1608X87N]
C27  0.1uF  [MURATA_GCM188-0603_CAPC]
C28  3.3uF  [CAPC200X125X145L30N]
C29  1uF  [CAPC160X80X90L30N]
C30  0.1uF  [MURATA_GCM188-0603_CAPC]
C31  .01uF  [CAPC1608X87N]
C32  1uF  [CAPC160X80X90L30N]
C33  10pF  [CAPC1608X90L23N]
C34  10pF  [CAPC1608X90L23N]
C35  0.1uF  [MURATA_GCM188-0603_CAPC]
C70  1.0uF  [CAPC1608X90N]
C71  1000.0pF  [CAPC1608X87N]
C72  0.10uF  [CAPC1608X87N]
C73  1.0uF  [CAPC1608X90N]
D3  LTST-C150KRKT  [LED_LTST-C150xxx]
D4  LTST-C150GKT  [LED_LTST-C150xxx]
JP1  87224-2  [TE_87224_2PIN]
JP2  87224-2  [TE_87224_2PIN]
R6  1.00K  [RESC1608X50N]
R7  1.00K  [RESC1608X50N]
R10  51  [RESC1608X50N]
R11  1.00M  [RESC1608X50N]
SB1  0603  [MISC_JUMPER_SM0603]
SB2  0603  [MISC_JUMPER_SM0603]
U8  TPS3836K33DBVT  [SOT95P280X145-5L25N]
U9  ASTMTXK-32.768KHZ-LG-T  [ABRACON_ASTMTXK]
U24  LT6656ACS6-3#TRMPBF  [LINEAR_S6]
Y1  16MHz  [XTALSC320X500X130L130N]
sheet 005 Miscellaneous Interfaces
C74  0.1uF  [MURATA_GCM188-0603_CAPC]
C75  1uF  [MURATA_GCM31M-1206_CAPC]
C76  0.1uF  [MURATA_GCM188-0603_CAPC]
J5  M80-8531042  [HARWIN_M80-853_10PIN]
JR1  1K  [MISC_0603-3P-JMPR]
R16  4.70K  [RESC1608X50N]
R17  4.70K  [RESC1608X50N]
SB3  0603  [MISC_JUMPER_SM0603]
U12  W25N01GVZEIG TR  [WINBOND_ZE_8PIN]
U13  MB85RC1MTPNF-G-JNERE1  [FUJITSU_FPT-8P-M02]
U25  BME280  [BOSCH_BME280]
sheet 006 pH ADC
C39  0.10uF  [CAPC1608X87N]
C40  10uF  [CAPC3216X180N]
C41  0.10uF  [CAPC1608X87N]
C42  0.10uF  [CAPC1608X87N]
Q1  MBT3946DW1T1G  [ONSEMI_SC-88_6PIN]
R18  TBD  [MBARI_TBD0603_RESC]
R19  10.0K  [RESC1608X50N]
R20  1.00M  [RESC1608X50N]
R21  1.00M  [RESC200X125X55L40N]
R22  1.00M  [RESC200X125X55L40N]
U14  ADS1248IPWR  [SOP28P65_970X640X120L62X24N]
sheet 007 Buffer
C43  TBD  [MBARI_TBD0603_CAPC]
C44  TBD  [MBARI_TBD0603_CAPC]
C45  TBD  [MBARI_TBD0603_CAPC]
C46  10,000.0pF  [CAPC1608X87N]
C47  1000.0pF  [CAPC1608X87N]
J6  31-70255  [AMP_31-70255]
R23  TBD  [MBARI_TBD0603_RESC]
R24  TBD  [MBARI_TBD0603_RESC]
R25  TBD  [MBARI_TBD0603_RESC]
R26  499.0K  [RESC1608X50N]
U15  ADG1609BCPZ-REEL7  [QFN17P50_300X300X80L40X24T160N]
U16  LMC6042AIMX/NOPB  [SOIC127P600X175-8L87N]  (sections A,B,C)
sheet 008 Bias
C48  1.0uF  [CAPC1608X90N]
C49  1000.0pF  [CAPC1608X87N]
C50  0.10uF  [CAPC1608X87N]
C51  1.0uF  [CAPC1608X90N]
C52  0.10uF  [CAPC1608X87N]
C53  1.0uF  [CAPC1608X90N]
C54  1000.0pF  [CAPC1608X87N]
C55  0.10uF  [CAPC1608X87N]
C56  10,000.0pF  [CAPC1608X87N]
J7  M80-8511242  [HARWIN_M80-851_12PIN]
R27  133  [RESC1608X50N]
R28  133  [RESC1608X50N]
R29  20.0K  [RESC1608X50N]
R30  15k  [PANASONIC_ERA3A_0603_RESC]
R31  100K  [VISHAY_CRCW-0603_RESC]
R32  1.00M  [RESC200X125X55L40N]
R33  6.65k  [PANASONIC_ERA3A_0603_RESC]
U17  LT6656ACS6-1.25#TRMPBF  [SOT95P280X100-6L20N]
U18  LT6656ACS6-1.25#TRMPBF  [SOT95P280X100-6L20N]

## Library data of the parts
C1 = CAP: CLASS: DISCRETE; Dielectric Type: Ceramic; Manufacturer: Kemet; Manufacturer PN: C0603C470J1GAC; PART_NUMBER: C0603C470J1GAC; Package Size: 0603; Rated Voltage: 100V; TMP Manufacturer: Kemet; TMP Manufacturer PN: C0603C470J1GAC; Temperature Coefficient: C0G(NP0); Tolerance: 5%
C2 C8 = CAP: CAP CER 10UF 16V 20% X7R 0805; CLASS: DISCRETE; Dielectric Type: Capacitors; Manufacturer: Taiyo Yuden; Manufacturer PN: EMK212BB7106MG-T; PART_NUMBER: EMK212BB7106MG-T; Package Size: 0805 (2012 Metric); Rated Voltage: 16V; TMP Manufacturer: Kemet; TMP Manufacturer PN: C1206C475K4RAC; Temperature Coefficient: X7R; Tolerance: ±20%
C3 C48 C51 C53 C70 C73 = CAP: CLASS: DISCRETE; Dielectric Type: Ceramic; Manufacturer: Kemet; Manufacturer PN: C0603C105K4RAC; PART_NUMBER: C0603C105K4RAC; Package Size: 0603; Rated Voltage: 16V; Temperature Coefficient: X7R; Tolerance: 10%
C4 = CAP: CAP CER 2.2UF 50V 10% X7R 0805; CLASS: DISCRETE; Dielectric Type: Capacitors; Manufacturer: Taiyo Yuden; Manufacturer PN: UMK212BB7225KG-T; PART_NUMBER: UMK212BB7225KG-T; Package Size: 0805 (2012 Metric); Rated Voltage: 50V; TMP Manufacturer: Kemet; TMP Manufacturer PN: C1206C225K4RACTU; Temperature Coefficient: X7R; Tolerance: ±10%
C5 C7 = CAP: CLASS: DISCRETE; Dielectric Type: Ceramic; Manufacturer: Kemet; Manufacturer PN: C0603C472K4RAC; PART_NUMBER: C0603C472K4RAC; Package Size: 0603; Rated Voltage: 16V; Temperature Coefficient: X7R; Tolerance: 10%
C6 C15 C18 = CAP: CAP CER 0.1UF 50V X7R 0508; CLASS: DISCRETE; Dielectric Type: Capacitors; Manufacturer: AVX Corporation; Manufacturer PN: 05085C104KAJ2A; PART_NUMBER: 05085C104KAJ2A; Package Size: 0508 (1220 Metric); Rated Voltage: 50V; Temperature Coefficient: X7R; Tolerance: 10%
C9-C14 C22-C25 C27 C30 C35 C74 C76 = CAP: CAP CER 0.1UF 50V X7R 0603; CLASS: DISCRETE; Manufacturer: Murata Electronics North America; Manufacturer PN: GCM188R71H104KA57J; PART_NUMBER: GCM188R71H104KA57J; Package Size: 0603 (1608 Metric); Rated Voltage: 50V; Temperature Coefficient: X7R; Tolerance: 10%
D1 D2 = DIODE_SBR: DIODE SBR 30V 2A POWERDI123; CLASS: DISCRETE; Manufacturer: Diodes Incorporated; Package Size: 2-SMD, Flat Lead; Rated Voltage: 450mV @ 2A; TMP Manufacturer: Diodes Incorporated
D5-D7 = DIODE_SCHOTTKY
D8 = DIODE_ZENER_ACx
J1-J3 = CON4: CONN HDR 2MM R/A W/LATCH 4POS; CLASS: IO; Manufacturer: Harwin Inc
R1 = RES: RES 10K OHM 1/10W 5% 0603 SMD; CLASS: DISCRETE; Manufacturer: Vishay/Dale; Manufacturer PN: CRCW060310K0JNEA; PART_NUMBER: CRCW060310K0JNEA; Package Size: 0603; Rated Power: 0.1W; TMP Manufacturer: Vishay; TMP Manufacturer PN: CRCW060310K0JNEA; Temperature Coefficient: 200ppm/K; Tolerance: 5%
R2 = RES: CLASS: DISCRETE; Manufacturer: Vishay; Manufacturer PN: CRCW0603200RJNEA; PART_NUMBER: CRCW0603200RJNEA; Package Size: 0603; Rated Power: 0.1W; TMP Manufacturer: Vishay; TMP Manufacturer PN: CRCW0603200RJNEA; Temperature Coefficient: 200ppm/K; Tolerance: 5%
R3 = RES: CLASS: DISCRETE; Manufacturer: Vishay; Manufacturer PN: CRCW0603140KFKEA; PART_NUMBER: CRCW0603140KFKEA; Package Size: 0603; Rated Power: 0.1W; TMP Manufacturer: Vishay; TMP Manufacturer PN: CRCW0603140KFKEA; Temperature Coefficient: 100ppm/K; Tolerance: 1%
R4 R5 R34 R35 = RES: RES SMD 100 OHM 1% 1/10W 0603; CLASS: DISCRETE; Manufacturer: Vishay; Manufacturer PN: CRCW0603100RFKEA; PART_NUMBER: CRCW0603100RFKEA; Package Size: 0603; Rated Power: 0.1W; Temperature Coefficient: 100ppm/K; Tolerance: 1%
T1 = WURTH_750311559: FLYBACK TRANSFORMER WE-FB LT8300; CLASS: DISCRETE; Manufacturer: Wurth Electronics Midcom; Package Size: 9.77mm L x 9.14mm W
TP1 TP3 = TESTPOINT: PC TEST POINT MINIATURE SMT; CLASS: DISCRETE; Manufacturer: Keystone Electronics; Package Size: 2.67 x 1.02 mm; TMP Manufacturer: Keystone Electronics
TP2 TP4 = TESTPOINT: PC TEST POINT MINIATURE SMT; CLASS: DISCRETE; Manufacturer: Keystone Electronics; Package Size: 2.67 x 1.02 mm
U1 = LT8300: IC REG FLYBACK ISO ADJ TSOT23-5; CLASS: IC; Manufacturer: Linear Technology; Package Size: SOT-23-5 Thin, TSOT-23-5; TMP Manufacturer: Linear Technology
U2 = ADuM1201: IC DGTL ISO 2CH LOGIC 8SOIC; CLASS: IC; Manufacturer: Analog Devices Inc; Package Size: 8-SOIC (0.154", 3.90mm Width); Supply Voltage: 2.7 V ~ 5.5 V
U3 = MAX3226E_TQFN-EP_16PIN: IC TRANSCEIVER FULL 1/1 16TQFN; CLASS: IC; Manufacturer: Maxim Integrated; Package Size: 16-WQFN Exposed Pad; Supply Voltage: 3V ~ 5.5V
U26 U28 = AQY2C2R2P
U27 = ADG841YKSZ
C16 C19 = CAP: CAP CER 2.2UF 50V 10% X7R 0805; CLASS: DISCRETE; Dielectric Type: Capacitors; Manufacturer: Taiyo Yuden; Manufacturer PN: UMK212BB7225KG-T; PART_NUMBER: UMK212BB7225KG-T; Package Size: 0805 (2012 Metric); Rated Voltage: 50V; Temperature Coefficient: X7R; Tolerance: ±10%
C17 C50 C52 C55 C72 = CAP: CAP CER 0.1UF 25V 10% X7R 0603; CLASS: DISCRETE; Dielectric Type: Ceramic; Manufacturer: Kemet; Manufacturer PN: C0603C104K3RACTU; PART_NUMBER: C0603C104K3RAC; Package Size: 0603; Rated Voltage: 25V; Temperature Coefficient: X7R; Tolerance: 10%
U4 U5 = ADM7160_UJ-5: IC REG LINEAR 3.3V 200MA TSOT5; CLASS: IC; Manufacturer: Analog Devices Inc.; Package Size: SOT-23-5 Thin, TSOT-23-5
U6 = LMC6042: IC OPAMP GP 100KHZ RRO 8SOIC; CLASS: IC; Group: 2; Manufacturer: Texas Instruments; Package Size: 8-SOIC (0.154", 3.90mm Width); Supply Voltage: 4.5 V - 15.5 V, 2.25 V - 7.75 V
U7 = TM4C123GH6PM: IC MCU 32BIT 256KB FLASH 64LQFP; CLASS: IC; Manufacturer: Texas Instruments; Package Size: 64-LQFP; Supply Voltage: 1.08V ~ 3.63V
C20 C21 C29 C32 = CAP: CAP CER 1UF 50V X5R 0603; CLASS: DISCRETE; Dielectric Type: Capacitors; Manufacturer: TDK Corporation; Manufacturer PN: C1608X5R1H105K080AB; PART_NUMBER: C1608X5R1H105K080AB; Package Size: 0603 (1608 Metric); Rated Voltage: 50V; Temperature Coefficient: X5R; Tolerance: 10%
C26 C31 = CAP: CAP CER 10000PF 50V X7R 0603; CLASS: DISCRETE; Dielectric Type: Ceramic; Manufacturer: Kemet; Manufacturer PN: C0603C103K5RAC; PART_NUMBER: C0603C103K5RAC; Package Size: 0603; Rated Voltage: 50V; Temperature Coefficient: X7R; Tolerance: 10%
C28 = CAP: CAP CER 3.3UF 6.3V X7R 0805; CLASS: DISCRETE; Dielectric Type: Capacitors; Manufacturer: TDK Corporation; Manufacturer PN: CGJ4J2X7R0J335K125AA; PART_NUMBER: CGJ4J2X7R0J335K125AA; Package Size: 0805 (2012 Metric); Rated Voltage: 6.3V; Temperature Coefficient: X7R; Tolerance: 10%
C33 C34 = CAP: CAP CER 10PF 50V C0G 0603; CLASS: DISCRETE; Dielectric Type: Capacitors; Manufacturer: TDK Corporation; Manufacturer PN: C1608C0G1H100D080AA; PART_NUMBER: C1608C0G1H100D080AA; Package Size: 0603 (1608 Metric); Rated Voltage: 50V; Temperature Coefficient: C0G, NP0; Tolerance: 0.5pF
C47 C49 C54 C71 = CAP: CLASS: DISCRETE; Dielectric Type: Ceramic; Manufacturer: Kemet; Manufacturer PN: C0603C102J3GAC; PART_NUMBER: C0603C102J3GAC; Package Size: 0603; Rated Voltage: 25V; Temperature Coefficient: C0G(NP0); Tolerance: 5%
D3 = LED: LED SUPER RED CLEAR 1206 SMD; CLASS: DISCRETE; LED Color: Red; Manufacturer: Lite-On Inc; Package Size: 1206 (3216 Metric); Rated Voltage: 2V
D4 = LED: LED GREEN CLEAR 1206 SMD; CLASS: DISCRETE; LED Color: Green; Manufacturer: Lite-On Inc; Package Size: 1206 (3216 Metric); Rated Voltage: 2.1V
JP1 JP2 = JUMPER: CONN HEADER VERT .100 2POS 15AU; CLASS: IO; Manufacturer: Tyco Electronics; Package Size: 0.318" (8.08mm)
R6 R7 = RES: RES 1.0K OHM 1/10W 5% 0603 SMD; CLASS: DISCRETE; Manufacturer: Vishay/Dale; Manufacturer PN: CRCW06031K00JNEA; PART_NUMBER: CRCW06031K00JNEA; Package Size: 0603; Rated Power: 0.1W; TMP Manufacturer: Vishay; TMP Manufacturer PN: CRCW0603270RJNEA; Temperature Coefficient: 200ppm/K; Tolerance: 5%
R10 = RES: RES SMD 51 OHM 5% 1/10W 0603; CLASS: DISCRETE; Manufacturer: Vishay; Manufacturer PN: CRCW060351R0JNEA; PART_NUMBER: CRCW060351R0JNEA; Package Size: 0603; Rated Power: 0.1W; Temperature Coefficient: 200ppm/K; Tolerance: 5%
R11 R20 = RES: RES SMD 1M OHM 5% 1/10W 0603; CLASS: DISCRETE; Manufacturer: Vishay; Manufacturer PN: CRCW06031M00JNEA; PART_NUMBER: CRCW06031M00JNEA; Package Size: 0603; Rated Power: 0.1W; Temperature Coefficient: 200ppm/K; Tolerance: 5%
SB1-SB3 = SB_JUMPER: MISC 2 PIN JUMPER SOLDER BRIDGE 0603; CLASS: IO; PART_NUMBER: MISC_SOLDERBRIDGE_SM0603
U8 = TPS3836: IC 2.93V LOW CURRENT MONSOT-23-5; CLASS: IC; Manufacturer: Texas Instruments; Package Size: SC-74A, SOT-753
U9 = ABRACON_ASTMTXK: OSC TCXO 32.768KHZ MEMS SMD; CLASS: DISCRETE; Frequency Stability: 5ppm; Manufacturer: Abracon LLC; Package Size: 0.061" L x 0.033" W (1.54mm x 0.84mm)
U24 = LT6656_S6: IC VREF SERIES 0.05% TSOT-23-6; CLASS: IC; Manufacturer: Linear Technology/Analog Devices; Package Size: SOT-23-6 Thin, TSOT-23-6
Y1 = CRYSTAL: CRYSTAL 16.0000MHZ 18PF SMD; CLASS: DISCRETE; Frequency Stability: 30ppm; Frequency Tolerance: 20ppm; Manufacturer: Abracon LLC; Manufacturer PN: ABM3-16.000MHZ-D2Y-T; PART_NUMBER: ABM3-16.000MHZ-D2Y-T; Package Size: 0.197" L x 0.126" W (5.00mm x 3.20mm)
C75 = CAP: CAP CER 1UF 50V X7R 1206; CLASS: DISCRETE; Manufacturer: Murata Electronics North America; Manufacturer PN: GCM31MR71H105KA55L; PART_NUMBER: GCM31MR71H105KA55L; Package Size: 1206 (3216 Metric); Rated Voltage: 50V; Temperature Coefficient: X7R; Tolerance: 10%
J5 = HEADER_10: CONN HDR 2MM DUAL W/LATCH 10POS; CLASS: IO; Manufacturer: Harwin Inc
JR1 = RES_3PIN-JMPR: 0603 3PIN JUMPER; CLASS: DISCRETE; PART_NUMBER: SM_0603-3P-JMPR; Package Size: 0603
R16 R17 = RES: RES SMD 4.7K OHM 5% 1/10W 0603; CLASS: DISCRETE; Manufacturer: Vishay; Manufacturer PN: CRCW06034K70JNEA; PART_NUMBER: CRCW06034K70JNEA; Package Size: 0603; Rated Power: 0.1W; Temperature Coefficient: 200ppm/K; Tolerance: 5%
U12 = W25N01GV_WSON: IC FLASH 1G SPI 104MHZ 8WSON; CLASS: IC; Manufacturer: Winbond Electronics; Package Size: 8-WDFN Exposed Pad; Supply Voltage: 2.7V ~ 3.6V
U13 = MB85RC1MT: IC FRAM 1M I2C 3.4MHZ 8SOP; CLASS: IC; Manufacturer: Fujitsu Electronics America, Inc.; Package Size: 8-SOIC (0.154", 3.90mm Width); Supply Voltage: 1.8V ~ 3.6V
U25 = BME280: SENSOR PRESSURE HUMIDITY TEMP; CLASS: IC; Manufacturer: Bosch Sensortec; Package Size: 8-VFLGA; Supply Voltage: 1.71 V - 3.6 V
C39 C41 C42 = CAP: CAP CER 0.1UF 50V X7R 0603; CLASS: DISCRETE; Dielectric Type: Ceramic; Manufacturer: Kemet; Manufacturer PN: C0603C104K5RAC; PART_NUMBER: C0603C104K5RAC; Package Size: 0603; Rated Voltage: 50V; Temperature Coefficient: X7R; Tolerance: 10%
C40 = CAP: CAP CER 10UF 16V 10% X7R 1206; CLASS: DISCRETE; Dielectric Type: Ceramic; Manufacturer: Kemet; Manufacturer PN: C1206C106K4RACTU; PART_NUMBER: C1206C106K4RAC; Package Size: 1206; Rated Voltage: 16V; Temperature Coefficient: X7R; Tolerance: 10%
Q1 = MBT3946DW1T1G: TRANS NPN/PNP 40V 0.2A SC88; CLASS: DISCRETE; Manufacturer: ON Semiconductor; Package Size: 6-TSSOP, SC-88, SOT-363; Polarity: NPN, PNP; Rated Power: 150mW
R18 R23-R25 = RES: TO BE DETERMINED, HEIGHT 0.022"; CLASS: DISCRETE; PART_NUMBER: TBD_R0603; Package Size: 0603
R19 = RES: RES SMD 10K OHM 1% 1/10W 0603; CLASS: DISCRETE; Manufacturer: Vishay; Manufacturer PN: CRCW060310K0FKEA; PART_NUMBER: CRCW060310K0FKEA; Package Size: 0603; Rated Power: 0.1W; Temperature Coefficient: 100ppm/K; Tolerance: 1%
R21 R22 R32 = RES: RES SMD 1M OHM 0.1% 1/8W 0805; CLASS: DISCRETE; Manufacturer: Panasonic Electronic Components; Manufacturer PN: ERA-6AEB105V; PART_NUMBER: ERA-6AEB105V; Package Size: 0805 (2012 Metric); Rated Power: 0.125W, 1/8W; Temperature Coefficient: 25ppm/C; Tolerance: 0.1%
U14 = ADS1248: IC ADC 24BIT SPI 2KSPS 28TSSOP; CLASS: IC; Manufacturer: Texas Instruments; Package Size: 28-TSSOP (0.173", 4.40mm Width); Supply Voltage: 2.7 V - 5.25 V
C43-C45 = CAP: TO BE DETERMINED, HEIGHT 0.035"; CLASS: DISCRETE; PART_NUMBER: TBD_C0603; Package Size: 0603
C46 C56 = CAP: CLASS: DISCRETE; Dielectric Type: Ceramic; Manufacturer: Kemet; Manufacturer PN: C0603C103J3GAC; PART_NUMBER: C0603C103J3GAC; Package Size: 0603; Rated Voltage: 25V; Temperature Coefficient: C0G(NP0); Tolerance: 5%
J6 = BNC_1C4S: CONN MINI BNC JACK R/A 75OHM PCB; CLASS: IO; Manufacturer: Amphenol RF Division
R26 = RES: CLASS: DISCRETE; Manufacturer: Vishay; Manufacturer PN: CRCW0603499KFKEA; PART_NUMBER: CRCW0603499KFKEA; Package Size: 0603; Rated Power: 0.1W; Temperature Coefficient: 100ppm/K; Tolerance: 1%
U15 = ADG1609B_CP: IC MULTIPLEXER DL 4X1 16LFCSP; CLASS: IC; Manufacturer: Analog Devices Inc.; Package Size: 16-WFQFN Exposed Pad, CSP
U16 = LMC6042: IC OPAMP GP 100KHZ RRO 8SOIC; CLASS: IC; Group: 1; Manufacturer: Texas Instruments; Package Size: 8-SOIC (0.154", 3.90mm Width); Supply Voltage: 4.5 V - 15.5 V, 2.25 V - 7.75 V
J7 = CON12: CONN HDR 2MM R/A W/LATCH 12POS; CLASS: IO; Manufacturer: Harwin Inc
R27 R28 = RES: CLASS: DISCRETE; Manufacturer: Vishay; Manufacturer PN: CRCW0603133RFKEA; PART_NUMBER: CRCW0603133RFKEA; Package Size: 0603; Rated Power: 0.1W; Temperature Coefficient: 100ppm/K; Tolerance: 1%
R29 = RES: CLASS: DISCRETE; Manufacturer: Vishay; Manufacturer PN: CRCW060320K0FKEA; PART_NUMBER: CRCW060320K0FKEA; Package Size: 0603; Rated Power: 0.1W; Temperature Coefficient: 100ppm/K; Tolerance: 1%
R30 = RES: RES SMD 15K OHM 0.1% 1/10W 0603; CLASS: DISCRETE; Manufacturer: Panasonic Electronic Components; Manufacturer PN: ERA-3AEB153V; PART_NUMBER: ERA-3AEB153V; Package Size: 0603 (1608 Metric); Rated Power: 0.1W, 1/10W; Temperature Coefficient: 25ppm/C; Tolerance: 0.1%
R31 = RES: RES 100K OHM 1/10W 1% 0603 SMD; CLASS: DISCRETE; Manufacturer: Vishay/Dale; Manufacturer PN: CRCW0603100KFKEA; PART_NUMBER: CRCW0603100KFKEA; Package Size: 0603; Rated Power: 0.1W; Temperature Coefficient: 100ppm/K; Tolerance: 1%
R33 = RES: RES SMD 6.65KOHM 0.1% 1/10W 0603; CLASS: DISCRETE; Manufacturer: Panasonic Electronic Components; Manufacturer PN: ERA-3AEB6651V; PART_NUMBER: ERA-3AEB6651V; Package Size: 0603 (1608 Metric); Rated Power: 0.1W, 1/10W; Temperature Coefficient: 25ppm/C; Tolerance: 0.1%
U17 U18 = LT6656_S6: IC VREF SERIES 1.25V TSOT23-6; CLASS: IC; Manufacturer: Linear Technology; Package Size: SOT-23-6 Thin, TSOT-23-6

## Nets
GND_ISO: C2.1 C3.1 C10.2 C15.2 C16.2 C17.2 C18.2 C19.2 C20.2 C21.2 C22.2 C23.2 C24.2 C25.2 C26.2 C27.2 C28.2 C29.2 C30.2 C31.2 C32.2 C33.2 C34.2 C35.2 C39.1 C40.1 C41.1 C42.1 C43.2 C44.2 C45.2 C46.2 C47.2 C48.2 C49.2 C50.2 C51.2 C52.2 C53.2 C54.2 C55.2 C70.2 C71.2 C72.2 C73.2 C74.2 C75.2 C76.2 J3.3 J5.2 J5.3 J5.5 J6.2(SHIELD) J6.3(SHIELD2) J6.4(SHIELD3) J6.5(SHIELD4) J7.4 J7.11 J7.12 JP1.2 JP2.2 Q1.1(E2) R6.1 R7.1 R22.2 R33.1 SB2.1 T1.5 T1.6 TP1.1(TP) U2.5(GND2) U4.2(GND) U5.2(GND) U6.4(V-) U7.3(GNDA) U7.12(GND1) U7.27(GND2) U7.35(GNDX) U7.39(GND3) U7.55(GND4) U8.2(Gnd) U9.1(GND1) U9.4(GND4) U12.4(GND) U13.2(A1) U13.3(A2) U13.4(VSS) U13.7(WP) U14.2(DGND2) U14.3(CLK) U14.7(REFP1) U14.8(REFN1) U14.10(VREFCOM) U14.21(AVSS) U15.1(Vss) U15.13(GND) U15.17(PAD) U16.4(V-) U17.1(GND) U17.2(GND) U18.1(GND) U18.2(GND) U24.1(GND) U24.2(GND) U25.1(GND) U25.5(SDO/ADDR) U25.7(GND) U26.2(IN-) U27.3(GND) U28.3(SA)
GND_SYS: C4.2 C6.2 C8.2 C9.2 C11.2 C14.2 D7.A D8.2(A) J1.3 J1.4 J2.3 J2.4 R1.2 T1.2 TP4.1(TP) U1.2(GND) U2.4(GND1) U3.11(GND) U3.17(EP) U28.2(IN-)
Vbat: C35.1 R10.1 U7.37(VBAT)
VDDC: C26.1 C27.1 C28.1 U7.25(VDDC1) U7.56(VDDC2)
+1P25V: C53.1 R31.2 R32.1 U14.15(AIN6/IEXC//GPIO6) U18.6(VOUT)
+2P5V: C48.1 R27.2 U17.6(VOUT)
+3P0V: C70.1 D6.A R10.2 R11.2 U9.3(VDD) U24.6(VOUT)
A0: R23.2 U14.5(REFP0/GPIO0)
A1: R25.2 U14.6(REFN0/GPIO1)
A3P3V: C17.1 C19.1 C42.2 R24.1 R29.1 U5.5(VOUT) U6.8(V+) U14.22(AVDD)
ADC_Reset: U7.5(PF4) U14.4(~{RESET})
Battery: C4.1 C6.1 J1.2 R2.1 T1.3 TP2.1(TP) U1.5(VIN) U26.4(SB)
Bias+: C49.1 C50.1 C51.1 C52.1 C54.1 C55.1 C71.1 C72.1 C73.1 J3.2 Q1.4(E1) U15.12(Vdd) U16.8(V+) U17.4(VIN) U18.4(VIN) U24.4(VIN)
C3P3V: C10.1 C16.1 C20.1 C21.1 C22.1 C23.1 C24.1 C25.1 C29.1 C30.1 C31.1 C32.1 C76.1 D5.A JR1.1 R16.1 R17.1 R18.1 SB1.2 SB3.1 U2.8(Vdd2) U4.5(VOUT) U7.2(VDDA) U7.11(VDD1) U7.26(VDD2) U7.42(VDD3) U7.54(VDD4) U8.5(Vdd) U12.3(~{WP}) U12.8(VCC) U13.8(VDD) U25.2(CSB) U25.6(VDDIO)
Counter A: J7.2 R30.1 U15.10(S2B)
Counter B: C56.1 R30.2 U15.3(S2A) U16.7(OUT)
drain: J7.9 R33.2 U16.5(IN+)
DRDY: U7.53(PD6) U14.25(~{DRDY})
EnvEnable: JR1.3 U7.57(PB5)
FLASH_CLK: U7.19(PA2) U12.6(CLK)
FLASH_CS: U7.20(PA3) U12.1(~{CS})
FLASH_HOLD: U7.24(PA7) U12.7(~{HOLD})
FLASH_MISO: U7.21(PA4) U12.2(DO)
FLASH_MOSI: U7.22(PA5) U12.5(DI)
Green_LED: D4.A U7.14(PC6)
HIB: R34.2 U7.33(~{HIB}) U27.4(IN)
Humidity: U7.7(PE2)
I3P5V: C8.1 C9.1 D2.C R5.2 U2.1(Vdd1) U3.9(FORCEON) U3.12(VCC) U3.13(~{FORCEOFF})
MISO: U7.63(PD2) U14.26(DOUT/~{DRDY})
MOSI: U7.64(PD3) U14.27(DIN)
NVRAM_SCL: R16.2 U7.47(PB2) U13.6(SCL) U25.4(SCK)
NVRAM_SDA: R17.2 U7.48(PB3) U13.5(SDA) U25.3(SDI/SDA)
OSC0: C33.1 U7.40(OSC0) Y1.1
OSC1: C34.1 U7.41(OSC1) Y1.2
PA0_Console_RX: U2.6(Vob) U7.17(PA0)
PA1_Console_TX: U2.7(Via) U7.18(PA1)
PC0_TCK: J5.7 U7.52(PC0)
PC1_TMS: J5.6 U7.51(PC1)
PC2_TDI: J5.9 U7.50(PC2)
PC3_TDO: J5.8 U7.49(PC3)
ph+: U14.14(AIN5/IEXC/GPIO5) U15.6(DA)
ph-: U6.6(IN-) U6.7(OUT) U14.12(AIN1/IEXC)
R3P5V: C2.2 C3.2 C5.2 C15.1 C18.1 D1.C TP3.1(TP) U4.1(VIN) U4.3(EN) U5.1(VIN) U5.3(EN)
Red_LED: D3.A U7.13(PC7)
ReferenceE: C46.1 J6.1(CENTER) R26.1
ReferenceI: J7.6
RESET: J5.10 U7.38(~{RST}) U8.4(\\~{RESE}T)
rko-a: J7.3
rko-b: J7.7
SCLK: U7.61(PD0) U14.28(SCLK)
Source: J7.1 R28.1 U15.2(S1A) U15.4(S3A)
SS: U7.62(PD1) U14.24(~{CS})
Start: U7.1(PB6) U14.23(START)
Substrate: J7.8 R32.2 U15.9(S3B)
T3: J7.5 R19.1
Temperature: U7.8(PE1)
Wake: JP1.1 R11.1 U7.32(~{WAKE}) U28.4(SB)
XOSC0: U7.34(XOSC0) U9.2(CLK)
N3536495: JP2.1 U8.3(\\~{M}R)
N3539619: SB1.1 SB2.2 U8.1(CT)
N3682711: D4.C R7.2
N3682795: D3.C R6.2
N3710447: C39.2 R18.2 U14.1(DVDD)
N3710661: C40.2 U14.9(VREFOUT)
N3725523: C41.2 R19.2 U14.11(AIN0/IEXC)
N3746895: C56.2 R31.1 U16.6(IN-)
N3747143: J7.10 R29.2
N3750476: C47.1 R26.2 U16.3(IN+)
N3750849: U15.11(S1B) U16.1(OUT) U16.2(IN-)
N3752723: U6.5(IN+) U15.7(DB)
N3754157: C43.1 R23.1 U15.15(A0)
N3754164: C44.1 R25.1 U15.14(A1)
N3775591: J5.1 SB3.2
N3866027: R20.2 U14.18(AIN3/IEXC/GPIO3)
N3866043: R21.2 R22.1 U14.16(AIN7/IEXC/GPIO7)
N3956660: C1.1 R2.2
N3956664: C1.2 R3.1 T1.4 U1.4(SW)
N3956790: D1.A R4.1 T1.7 T1.8
N3956898: R1.1 U1.1(EN) U26.3(SA)
N3956924: R3.2 U1.3(RFB)
N3956930: C5.1 R4.2
N3957299: C7.1 D2.A T1.1
N3957473: C7.2 R5.1
N3965186: U2.2(Voa) U3.8(T1IN)
N3965196: U2.3(Vib) U3.6(R1OUT)
N3965303: J2.2 U3.10(T1OUT)
N3965313: J2.1 R35.1 U3.5(R1IN)
N3974606: R27.1 R28.2
N3975191: C45.1 R24.2 U15.16(EN)
N3984624: C12.1 U3.16(C1+)
N3984631: C12.2 U3.1(C1-)
N3984641: C13.1 U3.2(C2+)
N3984649: C14.1 U3.4(V-)
N3984661: C11.1 U3.15(V+)
N3984842: C13.2 U3.3(C2-)
N3989093: Q1.5(B1) Q1.6(C2)
N3989219: Q1.2(B2) R20.1
N3989273: Q1.3(C1) R21.1
N4097201: C74.1 C75.1 JR1.2 U25.8(VDD)
N4114371: U26.1(IN+) U27.1(D)
N4114414: D5.C D6.C R34.1 U27.2(S) U27.6(VDD)
N4115004: D7.C D8.1(C) R35.2 U28.1(IN+)

Not connected (* = marked no-connect by the designer): J1 1; J3 1 4; J5 4*; U3 7(~{INVALID}) 14(READY); U4 4(NC); U5 4(NC); U7 4(PB7) 6(PE3) 9(PE0) 10(PD7) 15(PC5) 16(PC4) 23(PA6) 28(PF0) 29(PF1) 30(PF2) 31(PF3) 36(XOSC1) 43(PD4) 44(PD5) 45(PB0) 46(PB1) 58(PB4) 59(PE4) 60(PE5); U13 1(NC)*; U14 13(AIN4/IEXC/GPIO4) 17(AIN2/IEXC/GPIO2) 19(IEXC2) 20(IEXC1); U15 5(S4A) 8(S4B); U27 5(NC)

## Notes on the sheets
sheet 1
- A possible alternative is a Wurth 750311559
- DE9-S
  3
  2
  5
- Console Rx
  Console Tx
  Console Gnd
sheet 2
- Controller and digital power
- DuraFET isolated Bias power
- Analog and ADC power
sheet 3
- debug
- FRAM
sheet 4
- 200mS
- ~25nA
- 10mS
- Reset
- Place Y and C's close to TM4C
- Wake
- Change to 3.0V
- Place close to Pins 2 and 3
  VDDA and GNDA
- Place close to VDDC pins 25 and 56
- Place close to VDD and GND pins
- Place in general area TM4C
sheet 5
- Bus Address = 1110110x
  x = 0 Write
  x = 1 Read
- SPI Flash
- Debugger
- Non-Volatile Memory
- PB2
- PB3
- Bigger FRAM
- https://www.digikey.com/product-detail/en/fujitsu-electronics-america-inc/MB85RC1MTPNF-G-JNERE1/865-1268-1-ND/5456442
sheet 6
- GPIO1 GPIO0   Switch          AIN5         AIN1
    0     0        1         pH offset     Ext Ref
    0     1        2         Counter B     Counter A
    1     0        3         Source        Substrate
    1     1        4         pH offset     Int Ref
- GPIO3 -> Bias meas. Enable
- ISFET Temperature -> AIN0
  GND -> AIN6
  BIAS Battery -> AIN7
  Bias Battery Select -> GPIO3
                      -> float = Off
                      -> 0 = off (mphox Bias-)
                      -> 1 = Bias+
- Bias Battery Measurement
sheet 7
- A1    A0   Switch          SxA           SxB
  0     0        1           Source        Ext Ref
  0     1        2           Counter B     Counter A
  1     0        3           Source        Substrate
  1     1        4           NC            NC
sheet 8
- Change to 2.5V
- Change to 1.25
- 2.5V
- 188uA
- 50mV
- 266
- External electrode Reference potential
  FET Source terminal
  2.45V
- 1.25V
- 2.5-0.05-1.25 = 1.2V
- Substrate
- Virtual 1.25V
- 6.65k
- J1      Name                 Color
  1      Source              Orange
  2      Counter A           White/Black
  3      rko-a               Green
  4      T1                  Red/Black
  5      T3                  Orange/Black
  6      Reference           Black
  7      rko-b               Green/Black
  8      Substrate           Red
  9      Drain               Brown
  10     T2                  White
